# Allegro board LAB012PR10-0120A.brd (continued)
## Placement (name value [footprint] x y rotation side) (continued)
RV72  10K_0402_5%  [R_0402]  84.89 95.74 90 bottom
RV73  10K_0402_5%  [R_0402]  82.73 88.37 90 bottom
RV74  10K_0402_5%  [R_0402]  83.88 96.65 270 bottom
RV75  33_0402_5%  [R_0402]  82.86 96.65 270 bottom
RV76  33_0402_5%  [R_0402]  85.91 96.65 270 bottom
RV77  33_0402_5%  [R_0402]  79.23 90.35 0 bottom
RV78  33_0402_5%  [R_0402]  79.23 93.91 0 bottom
RV79  10K_0402_5%  [R_0402]  84.77 89.29 270 bottom
RV81  4.7K_0402_5%  [R_0402]  66.22 100.82 90 bottom
RV82  4.7K_0402_5%  [R_0402]  65.33 100.82 90 bottom
RV83  16.2K_0402_1%  [R_0402]  71.56 99.42 90 bottom
RV84  10K_0402_5%  [R_0402]  80.14 94.8 180 bottom
RV87  10K_0402_5%  [R_0402]  80.14 92.13 180 bottom
RV88  10K_0402_5%  [R_0402]  79.23 91.24 0 bottom
RV89  10K_0402_5%  [R_0402]  79.23 95.69 0 bottom
RV90  1K_0402_5%  [R_0402]  61.91 100.82 90 top
RV91  10K_0402_5%  [R_0402]  62.92 101.73 270 top
RV146  4.7K_0402_5%  [R_0402]  51.62 107.42 90 bottom
RV147  4.7K_0402_5%  [R_0402]  77.4 96.24 90 top
RV148  10K_0402_5%  [R_0402]  72.24 96.19 0 top
RV149  0_0402_5%  [R_0402]  72.24 97.08 0 top
RV150  10K_0402_5%  [R_0402]  60.56 91.88 0 top
RV151  10K_0402_5%  [R_0402]  62.85 101.73 270 bottom
RV152  10K_0402_5%  [R_0402]  61.96 100.82 90 bottom
RV153  0_0402_5%  [R_0402]  63.94 92.08 270 top
RV154  5.1K_0402_1%  [R_0402]  58.86 101.73 270 top
RV155  0_0402_5%  [R_0402]  79.23 88.57 0 bottom
RV156  0_0402_5%  [R_0402]  79.23 89.46 0 bottom
RV157  0_0402_5%  [R_0402]  79.23 93.02 0 bottom
RV158  0_0402_5%  [R_0402]  69.83 79.43 0 top
RV159  0_0402_5%  [R_0402]  69.83 80.7 0 top
RV160  0_0402_5%  [R_0402]  71.74 79.43 0 top
RV161  0_0402_5%  [R_0402]  71.74 80.7 0 top
RV162  4.7K_0402_5%  [R_0402]  79.89 77.02 180 bottom
RV163  4.7K_0402_5%  [R_0402]  78.97 76 0 bottom
RX2  100K_0402_5%  [R_0402]  8.82 76.59 270 top
RX3  100K_0402_5%  [R_0402]  8.74 74.73 0 top
RX7  0_0402_1%  [R0402_0OHM]  10.98 84.94 90 top
RX8  0_0402_5%  [R_0402]  10.09 84.94 90 top
RX9  10K_0402_5%  [R_0402]  4.17 80.07 0 top
RX10  10K_0402_5%  [R_0402]  24.46 74.88 270 top
RX12  10K_0402_5%  [R_0402]  197.21 74.22 0 top
RX13  100K_0402_5%  [R_0402]  199.89 84.08 270 top
RX14  100K_0402_5%  [R_0402]  197.21 75.11 0 top
RX15  150K_0402_5%  [R_0402]  197.21 73.33 0 top
RX16  2.2K_0402_5%  [R_0402]  196.35 76.38 0 top
RX17  2.2K_0402_5%  [R_0402]  196.35 77.53 0 top
RX21  0_0402_5%  [R_0402]  5.98 84.64 180 top
RX22  0_0402_5%  [R_0402]  5.98 85.65 180 top
RX23  0_0402_1%  [R0402_0OHM]  11.18 90.66 180 top
RX24  100K_0402_5%  [R_0402]  5.21 90.48 180 top
RX25  0_0402_1%  [R0402_0OHM]  9.45 93.6 270 top
RX26  100K_0402_5%  [R_0402]  4.17 81.08 0 top
RX27  0_0603_1%  [R0603_0OHM]  6.47 83.49 180 top
RX28  0_0603_1%  [R0603_0OHM]  9.65 99.12 0 top
RX29  0_0603_1%  [R0603_0OHM]  11.23 101.72 270 top
RX30  0_0603_5%  [R_0603]  9.71 101.72 270 top
RX34  20K_0402_5%  [R_0402]  198.13 72.45 180 top
RX35  100K_0402_5%  [R_0402]  5.21 89.29 180 top
RX36  0_0402_5%  [R_0402]  10.27 89.72 0 top
RX37  0_0402_5%  [R_0402]  7.55 104.65 270 top
RX38  0_0402_5%  [R_0402]  10.85 103.74 90 top
RX39  10K_0402_5%  [R_0402]  11.74 103.74 90 top
RX40  10K_0402_5%  [R_0402]  6.66 104.65 270 top
RX41  100K_0402_5%  [R_0402]  12.25 73.43 270 top
SW1  SMT1-05-A_4P  [SW_SMT1-05-A_4P]  172.28 113.17 90 top
T38  PAD  [TPC12]  143.19 89.74 0 top
T39  PAD  [TPC12]  118.9 93.68 0 top
T40  PAD  [TPC12]  117.58 94.09 0 top
T41  PAD  [TPC12]  120.07 94.92 0 top
T42  PAD  [TPC12]  116.03 93.78 0 top
T43  PAD  [TPC12]  120.17 93.32 0 top
T44  PAD  [TPC12]  117.66 88.73 0 top
T45  PAD  [TPC12]  119.18 89.23 0 top
T46  PAD  [TPC12]  120.55 89.26 0 top
T47  PAD  [TPC12]  118.4 87.43 0 top
T48  PAD  [TPC12]  118.5 90.66 0 top
T49  PAD  [TPC12]  120.86 86.49 0 top
T50  PAD  [TPC12]  119.06 92.23 0 top
T51  PAD  [TPC12]  120.02 90.89 0 top
T86  PAD  [TPC12]  57 98.32 0 top
T94  PAD~D  [TPC12]  173.59 106.63 0 bottom
T95  PAD~D  [TPC12]  175.42 107.17 180 top
T97  PAD  [TPC12]  163.38 87.89 0 top
T98  PAD  [TPC12]  155.89 89.21 0 top
T99  PAD  [TPC12]  158.35 87 0 top
T103  PAD~D  [TPC12]  154.97 83.06 0 top
T104  PAD~D  [TPC12]  153.98 87.18 0 top
T105  PAD  [TPC12]  154.56 84.95 0 top
T106  PAD  [TPC12]  156.9 83.62 0 top
T107  PAD  [TPC12]  152.18 87.18 0 top
T111  PAD  [TPC12]  117.86 98.4 0 top
T112  PAD  [TPC12]  116.44 98.4 0 top
T113  PAD  [TPC12]  120.07 96.45 0 top
T114  PAD  [TPC12]  116.95 96.75 0 top
T115  PAD  [TPC12]  117.46 95.36 0 top
T116  PAD  [TPC12]  118.55 96.91 0 top
T117  PAD  [TPC12]  155.07 87.96 0 top
T118  PAD~D  [TPC12]  150.42 81.72 0 top
T119  PAD~D  [TPC12]  150.22 83.16 0 top
T120  PAD~D  [TPC12]  147 100.26 0 top
T121  PAD~D  [TPC12]  148.65 100.26 0 top
T124  PAD~D  [TPC12]  158.73 92.99 180 bottom
T125  PAD~D  [TPC12]  158.27 90.17 180 bottom
T126  PAD~D  [TPC12]  153.12 86.21 0 top
T127  PAD~D  [TPC12]  157.79 85.15 0 top
T128  PAD~D  [TPC12]  156.9 81.72 0 top
T129  PAD~D  [TPC12]  143.06 95.56 0 top
T130  PAD~D  [TPC12]  141.48 95.48 0 top
T131  PAD~D  [TPC12]  141.59 93.91 0 top
T132  PAD~D  [TPC12]  128.48 82.55 0 top
T133  PAD~D  [TPC12]  146.28 92.05 0 top
T134  PAD~D  [TPC12]  128.96 80.7 0 top
T135  PAD~D  [TPC12]  148.75 101.76 0 top
T136  PAD~D  [TPC12]  159.11 85.15 0 top
T137  PAD~D  [TPC12]  150.27 84.44 0 top
T138  PAD~D  [TPC12]  143.08 99.78 0 top
T139  PAD~D  [TPC12]  153.19 81.69 0 top
T140  PAD~D  [TPC12]  142.73 98.18 0 top
T141  PAD~D  [TPC12]  150.07 80.4 0 top
T142  PAD~D  [TPC12]  147.38 81.34 0 top
T143  PAD~D  [TPC12]  143.47 96.93 0 top
T144  PAD~D  [TPC12]  147.25 79.33 0 top
T145  PAD~D  [TPC12]  148.65 79.05 0 top
T146  PAD~D  [TPC12]  113.11 74.99 0 top
T147  PAD~D  [TPC12]  112.96 78.87 0 top
T148  PAD~D  [TPC12]  115.12 101.53 0 top
T149  PAD~D  [TPC12]  116.52 101.53 0 top
T150  PAD~D  [TPC12]  129.67 103.51 0 top
T151  PAD~D  [TPC12]  125.63 105.36 0 top
T152  PAD~D  [TPC12]  124.59 103.38 0 top
T153  PAD~D  [TPC12]  114.81 93.4 0 top
T154  PAD~D  [TPC12]  118.75 95.15 0 top
T155  PAD~D  [TPC12]  141.71 92.33 0 top
T156  PAD~D  [TPC12]  143.21 91.11 0 top
T157  PAD~D  [TPC12]  111.74 76.97 0 top
T158  PAD~D  [TPC12]  119.31 103.05 0 top
T159  PAD~D  [TPC12]  153.26 102.73 0 top
T160  PAD~D  [TPC12]  144.79 93.02 0 top
T161  PAD~D  [TPC12]  157.41 99.59 0 top
T162  PAD~D  [TPC12]  143.36 92.41 0 top
T163  PAD~D  [TPC12]  157.41 100.96 0 top
T164  PAD~D  [TPC12]  146.75 98.77 0 top
T165  PAD~D  [TPC12]  145.98 97.46 0 top
T166  PAD~D  [TPC12]  110.6 74.3 0 top
T167  PAD~D  [TPC12]  155.87 102.65 0 top
T168  PAD~D  [TPC12]  154.83 103.44 0 top
T169  PAD~D  [TPC12]  117.15 103.94 0 top
T170  PAD~D  [TPC12]  116.16 102.93 0 top
T171  PAD~D  [TPC12]  158.55 81.46 0 top
T172  PAD~D  [TPC12]  157.28 80.19 0 top
T173  PAD~D  [TPC12]  110.83 75.9 0 top
T174  PAD~D  [TPC12]  153.35 90.99 0 top
T175  PAD~D  [TPC12]  154.36 95.31 0 top
T176  PAD~D  [TPC12]  152.14 98.28 0 top
T177  PAD~D  [TPC12]  151.67 94.72 0 top
T178  PAD~D  [TPC12]  147.63 102.42 0 top
T179  PAD~D  [TPC12]  158.04 96.45 0 top
T180  PAD~D  [TPC12]  158.04 98.34 0 top
T181  PAD~D  [TPC12]  158.07 98.99 180 bottom
T182  PAD~D  [TPC12]  153.27 84.48 0 top
T201  -  [TPC12]  62.16 89.72 0 top
T202  -  [TPC12]  59.77 89.87 0 top
T203  -  [TPC12]  71.56 91.5 0 top
T204  -  [TPC12]  67.98 89.97 0 top
T205  -  [TPC12]  70.8 92.64 0 top
T206  -  [TPC12]  72.83 90.86 0 top
T207  -  [TPC12]  69.2 90.43 0 top
T208  -  [TPC12]  70.19 94.24 0 top
T209  -  [TPC12]  71.35 90.15 0 top
T210  -  [TPC12]  69.27 93.02 0 top
T211  -  [TPC12]  68.23 91.7 0 top
T212  -  [TPC12]  66.99 91.11 0 top
T213  -  [TPC12]  67.49 92.79 0 top
T214  -  [TPC12]  67.11 94.09 0 top
T215  -  [TPC12]  69.14 95.69 0 top
T216  -  [TPC12]  65.72 90.73 0 top
T217  -  [TPC12]  66.07 92.54 0 top
T218  -  [TPC12]  70.16 85.65 0 top
T221  -  [TPC12]  67.62 95.31 0 top
T222  -  [TPC12]  69.53 97.08 0 top
T223  -  [TPC12]  62.24 98.23 180 bottom
T224  -  [TPC12]  62.83 96.88 180 bottom
T3861  PAD~D  [TPC12]  174.94 63.33 0 top
T3862  PAD~D  [TPC12]  176.21 63.56 0 top
T4927  PAD~D  [TPC12]  182.35 65.51 180 top
T4928  PAD~D  [TPC12]  183.7 65.46 180 top
T4929  PAD~D  [TPC12]  184.69 68.71 180 top
T4930  -  [TPC12]  76.64 89.97 180 bottom
TL2  350UH_LF-H1201P-2  [LANKO_LF-H1201P-2_16P]  180.59 102.04 90 bottom
U1  S IC SN74AVC2T45DCTR_SM8  [SN74LVC2T45DCTR_SM8]  81.63 94.31 0 bottom
U2301  -  [TPS22966DPUR_SON14_2X3]  169.42 13.13 0 top
U2302  64M EN25Q64-104HIP SOP 8P  [W25Q64FVSSIG_SO8]  184.08 18.6 180 bottom
U2303  -  [74AUP1G07GW_TSSOP5]  135.43 55.44 270 top
U2304  -  [TPS22966DPUR_SON14_2X3]  160.78 13.13 0 top
U2407  F75303M_MSOP10  [EMC1403-2-AIZL-TR_MSOP10]  154.76 8.32 0 top
U2408  TPS22967DSGR_SON8_2X2  [AOZ1336_DFN8_2X2]  154.73 22.62 180 top
UA1  -  [ALC3234-CG_MQFN48_6X6]  198.73 16.44 180 bottom
UC1  HASWELL-MCP-E-ULT_BGA1168  [HASWELL-MCP-E-ULT_BGA_1168P-T]  156.14 102.04 0 bottom
UC3  -  [MC74VHC1G08DFT2G_SC70-5]  171.25 94.04 270 top
UC4  -  [74CBTLV3126BQ_DHVQFN14_2P5X3]  88.52 86.97 90 top
UE1  KB9012QF-A4_LQFP128_14X14  [KB9012QF-A2_LQFP128_14X14]  130.99 17.71 270 top
UE2  -  [SN74LVC1G06DCKR_SC70-5]  110.66 25.87 180 top
UE3  APE8875M SOP 8P  [G993P1UF_SOP8]  6.79 69.57 180 top
UE4  TPS22967DSGR_SON8_2X2  [AOZ1336_DFN8_2X2]  8.82 65.08 270 top
UG1  -  [SLG3NB274VTR_TQFN16_2X3]  187.39 77.85 90 top
UI2  -  [AP2301MPG-13_MSOP8]  190.69 40.65 270 top
UI3  -  [AP2301MPG-13_MSOP8]  190.69 54.12 270 top
UI4  -  [AP2301MPG-13_MSOP8]  26.26 38.55 0 top
UI5  -  [SY6288D20AAC_SOT23-5]  194.21 46.92 90 top
UI6  -  [SY6288D20AAC_SOT23-5]  194 43.24 90 top
UI7  -  [SY6288D20AAC_SOT23-5]  24.69 41.5 180 top
UL1  RTL8106E-CG QFN 32P E-LAN CTRL  [RTL8106EUS-CG_QFN32_4X4]  177.62 104.96 270 bottom
UL2  -  [APL3512ABI-TRG_SOT23-5]  168.27 114.02 180 bottom
UL3  -  [SY6288C20AAC_SOT23-5]  189.47 95.63 180 bottom
UM1  -  [SY6288C20AAC_SOT23-5]  196.19 74.82 90 bottom
US2  -  [PS8520BTQFN20GTR2_TQFN20_4X4]  187.12 10.87 90 top
US3  LNG3DMTR_LGA16_3X3~D  [LNG3DMTR_LGA16_3X3]  20.36 16.86 180 bottom
UV1  2160856030-A0_FCBGA631  [216-0842024-A11-MAR_FCBGA_631P]  53.2 94.5 270 bottom
UV2  -  [MC74VHC1G08DFT2G_SC70-5]  78.18 77.84 180 top
UV3  -  [ADM1032ARMZ_MSOP8]  57.91 109.67 270 bottom
UV5  H5TC2G63FFR-11C FBGA 96P  [K4W1G1646E-HC12_FBGA_96P-A39]  42.95 72.12 90 bottom
UV6  H5TC2G63FFR-11C FBGA 96P  [K4W1G1646E-HC12_FBGA_96P-A39]  42.95 78.52 270 top
UV7  H5TC2G63FFR-11C FBGA 96P  [K4W1G1646E-HC12_FBGA_96P-A39]  42.95 98.33 270 top
UV8  H5TC2G63FFR-11C FBGA 96P  [K4W1G1646E-HC12_FBGA_96P-A39]  42.95 91.93 90 bottom
UX1  -  [APL3512ABI-TRG_SOT23-5]  12.06 83.57 180 top
UX3  -  [APL3512ABI-TRG_SOT23-5]  9.5 97.27 270 top
UX4  -  [SY6288C20AAC_SOT23-5]  21.27 74.08 0 top
YC1  32.768KHZ_12.5PF_Q13FC1350000  [Y_Q13FC1350000_2P]  176.08 74.08 270 top
YC2  24MHZ_12PF_X3G024000DC1H  [Y_X3G024000DC1H_4P]  136.79 109.31 180 bottom
YG1  25MHZ_10PF_7V25000014  [Y_FSX3M-25PM20FDO_4P]  187.47 74.52 180 top
YL2  25MHZ_10PF_7V25000014  [Y_FSX3M-25PM20FDO_4P]  176.8 108.6 180 bottom
YV1  27MHZ_10PF_7V27000050  [Y_7V27000011_4P]  82.57 73.8 270 bottom

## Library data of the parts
C35-C38 C50-C58 C61-C64 C67-C69 C71 C73 C75-C77 C79-C81 C83 C85 C87-C93 C2326 C2327 C2498 C2500 C2502 C2504 C2505 C4311-C4314 C4321 C4322 C5212-C5219 CA21 CA32 CA38-CA40 CA54 CA56 CA58 CA60 CA65 CA69 CC14-CC16 CC23 CC24 CC36 CC41 CC42 CE58-CE61 CG2-CG4 CG7-CG10 CI2 CI9 CI15 CI26 CI45-CI47 CL3 CL5-CL9 CL12 CL16 CL30 CL31 CL36 CL37 CL39 CL41 CM5 CM7 CM8 CS5 CS6 CS27 CS30-CS37 CS42 CS43 CV15 CV20 CV24 CV25 CV28 CV29 CV33 CV34 CV39-CV42 CV46-CV49 CV63-CV65 CV112 CV115-CV117 CV129-CV135 CV137-CV143 CV154 CV155 CV158-CV168 CV170-CV183 CVT90 CX1 CX2 CX4 CX9 CX11-CX21 CX23-CX30 CX50 CX52 PC2 PC7 PC8 PC13-PC17 PC108 PC116 PC117 PC202 PC210 PC214 PC520-PC523 PC526 PC527 PC529-PC531 PC541 PC545 PC546 PC548 PC601 PC603 PC604 PC733 PC840-PC852 PC859 PC860 PC869 PC871 PC872 PC1019 PC1022 PC1025 PC1027 PC1028 PC1030 PC1031 PC1033 PC1034 PC1036 PC1040 PC1042 PC1045 PC1047 PC1050 PC1051 PC1100 PC1101 PC1104 PC1106 PC1302 PC1304 PC1306 PC1307 = C_0402
C39-C47 C60 C66 C72 C74 C78 C82 C2305 C2306 C2308 C2309 C2311-C2318 C2322-C2325 C2328 C2329 CA55 CA57 CA59 CA61-CA64 CA67 CA68 CA71 CA74 CC37 CC38 CE56 CE57 CG6 CI40 CI43 CL4 CL13 CL14 CL17 CL38 CM4 CM6 CV19 CV38 CV43-CV45 CV67 CV68 CV118 CV136 CV151 CV169 CX5 CX22 PC103 PC104 PC106 PC312 PC313 PC525 PC528 PC853-PC858 PC1020 PC1021 PC1026 PC1029 PC1032 PC1035 PC1043 PC1044 PC1103 PC1105 = C_0603
C59 C65 C70 C84 C86 CL33 CM3 = C_1206
C2307 C2310 CG5 CI18 CI44 CS7 CS44 CX3 CX7 CX8 CX49 CX51 PC112 PC206 PC311 PC524 PC532 PC600 PC602 PC605 PC730 PC731 PC734-PC739 PC905-PC912 PC918-PC921 PC1023 PC1024 PC1041 PC1046 PC1048 PC1049 PC1052 PC1102 PC1300 PC1301 PC1303 PC1305 PC1308 = C_0805
CA1 CA2 = C_0603: room: AJACK
CA22 CA24 CA25 CA29-CA31 CA33 CA51 CV62 = C_0402: room: CODEC
CA23 CA53 CV61 = C_0603: room: CODEC
CC1-CC5 CC8 CC11 CC13 CC17-CC22 CC25 CC27-CC35 CC40 PC207 PC914 = C_0402: room: CPU
CC6 CC7 CC9 CC10 = C_0402: room: SPI
CC26 = C_0603: room: CPU
CD1-CD11 CD21-CD27 CD30-CD42 CD52-CD57 CD60 CD61 CD64 = C_0402: room: MEMORY
CD12-CD14 CD16-CD20 CD28 CD29 CD43-CD50 CD58 CD59 CD62 = C_0603: room: MEMORY
CD15 CD51 = C_D3: room: MEMORY
CD63 CD65 = C_D3
CE1 CE2 CE5-CE9 = C_0402: room: SIO
CE11 CE12 CE15 CE18-CE20 CE23 CE24 CE26-CE31 CE34 = C_0402: room: KBC
CE16 = C_0805: room: KBC
CE22 CE25 = C_0603: room: KBC
CE32 = C_0402: room: FAN
CE35 CE36 = C_0402: room: THERMAL
CI1 CI8 = C_MP6VLPS220MC4R2: room: USB
CI3 CI4 CI7 CI10 CI11 CI13 CI14 CI17 = C_0402: room: USB
CI6 CI12 = C_0805: room: USB
CL15 = C_0402: room: LAN
CL19 CV17 CV18 CV21 CV23 CV26 = C_0402: room: HDMI
CMOS1 = SHORTPADS: User Part Number: PART#; room: CPU
CV1-CV11 = C_0402: room: EDP
CV22 CV27 = C_0603: room: HDMI
CV50-CV53 CV56-CV59 CV124-CV128 CV144 = C_0402: room: CRT
CV54 CV55 = C_0603: room: CRT
CV60 CV66 CV71-CV80 CV145-CV150 CV152 CV153 CV156 CV157 = C_0402: room: DP12412
CV69 CV70 = C_0603: room: DP12412
CV81 = C_0603: room: TOUCH
CV82 CV85-CV87 CV89 CV90 CV92-CV102 CV104-CV111 CV113 CV114 = C_0402: room: DP2320
CV83 CV84 CV88 CV91 CV103 = C_0603: room: DP2320
CV119-CV123 = C_0402: room: DP125
DA8 = BAT54C-7-F_SOT23-3
DA10 DA12-DA14 = AZ5125-02SPR7G_SOT23-3
DC1 = BAT54CW_SOT323-3
DE1 = L03ESDL5V0CG3-2_SOT-523-3: room: FAN
DE2 = L03ESDL5V0CC3-2_SOT23-3
DE3 DE4 DH1 DX1 = RB751V-40_SOD323-2
DI1 DI4 = IP4292CZ10-TBR_XSON10_2P5X1: room: USB
DI2 DI5 = L30ESDL5V0C3-2_SOT23-3: room: USB
DS1 = SDM10U45-7_SOD523-2
DX2 = PESD5V0U2BT_SOT23-3
FD1-FD4 = FIDUCIAL_C40M80: room: LED
FE1 = F_1812L075-24DR
FX1 = F_1206L150PR
H1 H20 = H_2P8N: room: LED
H2-H8 H11 H12 = H_2P8: room: LED
H9 = H_2P8
H10 = H_3P0
H13-H16 = H_3P6: room: LED
H17-H19 = H_3P3: room: LED
H21 = H_2P8N
H22 = H_2P8X3P3N
H23 = H_2P8X4P8N
HE1 LV2 LV4 LV7 LV8 LV26 PH1 PH1002 PH1003 PR3 PR4 PR20 PR23-PR37 PR110 PR115 PR204 PR304 PR309 PR310 PR525 PR533 PR537 PR543 PR545 PR549 PR551 PR558 PR602-PR604 PR719 PR727 PR1020 PR1025 PR1029-PR1033 PR1035 PR1037 PR1038 PR1040-PR1048 PR1051-PR1053 PR1056 PR1058 PR1059 PR1102 PR1105 PR1107 PR1108 PR1110 PR1300-PR1302 PR1304 R1 R2 R10 R16 R159 R286 R2313 R2318 R2329-R2338 R2341 R2346-R2352 R2354 R2356-R2359 R2448 R2450-R2453 RA10-RA13 RA19 RA53 RA55 RA56 RA79-RA84 RA130 RA165 RA166 RA1109 RA1112 RA1113 RC3 RC5 RC6 RC12 RC13 RC24 RC27 RC28 RC32 RC36 RC39 RC48 RC49 RC51 RC52 RC56 RC58 RC60 RC64 RC71 RC73 RC75 RC76 RC79 RC84 RC90 RC97 RC100 RC101 RC104 RC105 RC107-RC111 RC114 RC115 RC134-RC138 RC142 RC143 RC362-RC364 RC367 RC368 RE1-RE3 RE7 RE18 RE47 RE49 RE50 RE72 RE73 RE326 RE329 RE332-RE335 RE338-RE340 RG1-RG6 RG8 RL27 RL31 RL33-RL35 RL37-RL40 RM8-RM10 RS8 RS18-RS38 RV21-RV23 RV25 RV26 RV28 RV29 RV39-RV49 RV59 RV146-RV163 RX2 RX3 RX8-RX10 RX12-RX17 RX21 RX22 RX24 RX26 RX34-RX41 = R_0402
J9 J518-J520 JP3 JP12 JP14 PJP301 = JUMP_43X39
J510-J516 JP13 PJP600 PJP601 PJP1300 PJP1301 = JUMP_43X79
JDIMM1 = BELLW_80001-1021_204P: room: CPU
JDIMM2 = BELLW_80011-1021_204P: room: CPU
JEDP = STARC_107K40-000001-G2_40P
JFAN = ACES_88231-03041_3P
JHDD = E-T_4260K-F10N-00L_10P
JHDMI = CONCR_099ATAC19NBLCNF_19P
JHP = SINGA_2SJ3080-001111F_6P
JIO = ACES_51524-0160N-001_16P
JKB = HB_A823020-SBHR21_30P
JKBBL = ACES_50524-00401-P01_4P-T
JLAN = SDAN_601028-008041_8P-T
JLED JTP = ACES_51524-0080N-001_8P
JNGFF = LOTES_APCI0019-P009A_67P
JRTC = ACES_50271-0020N-001_2P
JSPK = ACES_50278-00401-001_4P
JTP1 = ACES_51524-0100N-001_10P
JUSB1 JUSB2 = TAITW_PUBAU6-09FLBS1NN4H0_9P: room: USB
JXDP1 = SAMTE_BSH-030-01-L-D-A_60P: room: CPU
L1-L5 LL1 = MURAT_LQM2MPN2R2NG0L_2P
LA1 = MURAT_BLM15BB221SN1D_2P
LA3 = R_0603: room: AJACK
LA4 PR210 PR538 PR605 PR1024 PR1034 PR1039 PR1055 PR1057 PR1101 R245 R2314 R2315 RE328 RE330 RE331 RV24 RV60 RX30 = R_0603
LA5 LA6 = R_0603: room: CODEC
LA7 = MURAT_BLM15BD601SN1D_2P: room: CODEC
LA8 LA9 = KC_FBMA-L10-160808-800LMT_2P: room: CODEC
LA10 = MURAT_BLM15BD601SN1D_2P
LE1 LE2 = KC_FBMA-L11-160808-800LMT_2P
LI1 LI3 LI4 LI6 = MURAT_DLW21SN670HQ2L_4P: room: USB
LI2 LI5 = KC_WCM-2012HS-900T_4P: room: USB
LI7 LI8 LX2-LX6 = KC_WCM-2012HS-900T_4P
LV3 RV8 RV9 RV11-RV13 RV15-RV17 RV20 = R_0402: room: HDMI
LV6 = MURAT_BLM15BB221SN1D_2P: room: HDMI
LV25 RV73-RV79 RV81-RV84 RV87-RV89 = R_0402: room: DP2320
LX1 = KC_FBMA-L11-201209-221LMA30_2P
PBATT = ALLTO_C144LS-109A9-L_9P-T
PC1 PC3-PC5 = C_0402: room: P_DCIN
PC100 PC105 PC109-PC111 PC200 PC204 PC209 PC301 PC302 PC401 = C_0603: room: ETY-ROOM
PC101 = C_MP6VLPS220MC4R2: room: ETY-ROOM
PC102 PC114 PC201 PC203 PC300 PC303 PC304 PC307 PC400 PC402 PC403 PC500 PC510 PC519 = C_0402: room: ETY-ROOM
PC107 = C_MP6VLPS220MC4R2
PC113 = C_0402: room: 3V5V
PC115 = C_0805: room: 3V5V
PC205 PC211 PC212 PC305 PC306 PC308-PC310 PC404 = C_0805: room: ETY-ROOM
PC208 = C_0402: room: ADP3209
PC213 = C_MP6VU330MC6: room: CPU_CORE
PC515 PC516 = C_EEEFZ1E101P: room: CPU_CORE
PC517 PC518 = C_0805: room: CPU_CORE
PC701 PC702 PC705-PC708 PC711 PC715 PC717 PC720 PC723-PC728 = C_0402: room: CHARGER
PC703 PC704 PC712-PC714 PC716 PC718 = C_0805: room: CHARGER
PC709 PC710 PC719 PC722 = C_0603: room: CHARGER
PC721 = C_0603: room: ADP3209
PC729 = C_0805: room: P_SELECTOR
PC732 = C_EEEFZ1E101P
PC836-PC839 = C_D2
PC901-PC904 PC913 PC915-PC917 PC922 PC923 = C_0805: room: CPU
PC924 = C_D2: room: CPU
PC1108 = C_MP6VU330MC6
PD1 PD2 = TVNST52302AB0_SOT523-3: room: ETY-ROOM
PD101 = TVNST52302AB0_SOT523-3
PD700 = BAS40CW_SOT323-3
PH500 PH501 PR102 PR104-PR108 PR114 PR205 PR207 PR208 PR301 PR305 PR307 PR400-PR403 PR500 PR512 PR528 PR539 PR701 PR706 PR707 = R_0402: room: ETY-ROOM
PJP100-PJP102 PJP300 = JUMP_43X118: room: ETY-ROOM
PJP103 PJP1100 PJP1101 = JUMP_43X118
PJP200 = JUMP_43X118: room: DDR_VTT_0.75V
PJP201 = JUMP_43X118: room: VGA_CORE
PJP203 = JUMP_43X39: room: ETY-ROOM
PJP400 PJP401 = JUMP_43X79: room: VGA_CORE
PJPDC = ACES_50299-00501-003_5P
PL1 PL3 PL4 = TAIYO_FBMJ4516HS720NT_2P: room: P_DCIN
PL2 = MURAT_BLM15AG102SN1D_2P: room: P_DCIN
PL5 PL201 PL302 PL1000 PL1100 = TAIYO_FBMJ4516HS720NT_2P
PL6 PL7 PL503 PL1004 = CYNTE_PCMB053T-1R0MS_2P-S
PL100 PL101 PL200 = PANAS_ETQP3W2R2WFN_2P: room: ETY-ROOM
PL102 = L_5X5X3_M_2P: room: VDDCI
PL301 = L_5X5X3_M_2P: room: ETY-ROOM
PL501 = TAIYO_FBMJ4516HS720NT_2P: room: CPU_CORE
PL502 = TOKO_FDUE1040J-H-R36M-P3_4P
PL600 = TAIYO_NRS4018T1R0NDGJ_2P
PL701 = CYNTE_PCMB104T-1R0MH_2P: room: ETY-ROOM
PL702 = L_5X5X3_M_2P
PL1002 PL1003 = PANAS_ETQP4LR15AFM_4P
PL1101 PL1300 = PANAS_ETQP3W2R2WFN_2P
PQ1-PQ3 = 2N7002DW-T-R7_SOT363-6: room: P_DCIN
PQ4 = 2N7002DW-T-R7_SOT363-6: room: ETY-ROOM
PQ5 = RHU002N06_SOT323-3
PQ6 = FDV301N_NL_SOT23-3: room: ETY-ROOM
PQ101-PQ103 = SIS412DN-T1-GE3_POWERPAK8-5: room: ETY-ROOM
PQ104 PQ200 PQ201 PQ1100 PQ1101 = SIS412DN-T1-GE3_POWERPAK8-5
PQ501 = CSD86350Q5D_SON8
PQ700 = AO4407AL_SO8: room: CHARGER
PQ701 = AO4409L_SO8: room: ETY-ROOM
PQ702 = AO4407AL_SO8: room: ETY-ROOM
PQ703 = SIR472DP-T1-GE3_POWERPAK8-5: room: ETY-ROOM
PQ705 = SIRA06DP-T1-GE_POWERPAKSO-8-5
PQ706 = 2N7002DW-T-R7_SOT363-6
PQ1003 PQ1005 = MDU1516URH_POWERDFN56-8-5
PQ1004 PQ1006-PQ1008 = SIR472DP-T1-GE3_POWERPAK8-5
PR1 PR2 PR6-PR11 PR15 PR16 PR18 = R_0402: room: P_DCIN
PR5 PR1036 PR1054 PR1104 PR1303 RM7 = R_1206
PR100 PR101 PR201 PR202 = R0402_0OHM: room: ETY-ROOM
PR103 PR111 PR206 PR536 = R_0603: room: ETY-ROOM
PR109 PR519 = R_0402: room: CPU_CORE
PR112 PR113 PR203 PR302 PR534 PR722 = R_1206: room: ETY-ROOM
PR200 = R_0603: room: CPU_CORE
PR209 PR300 PR552 PR601 PR1022 PR1027 PR1049 PR1050 PR1060-PR1063 PR1103 R248 R250 R251 R416 RC26 RC37 RC41-RC46 RC57 RC59 RC82 RC365 RC366 RD1 RD8 RE44 RE336 RE337 RM5 RM6 RX7 RX23 RX25 = R0402_0OHM
PR303 = R0603_0OHM: room: ETY-ROOM
PR306 PR308 = R_0402: room: 1P5V
PR503 PR504 PR507 PR521 PR535 = R_0402: room: GPU_CORE
PR505 PR506 PR508 PR510 PR511 = R0402_0OHM: room: GPU_CORE
PR702 = R_1206_4P-D: room: ETY-ROOM
PR704 PR708 PR711 PR713 PR717 PR718 PR723-PR726 PR728 = R_0402: room: CHARGER
PR705 PR720 = R_1206: room: CHARGER
PR709 PR710 = R_0603: room: CHARGER
PR712 = R_0402: room: 3V5V
PR714 PR715 = R0402_0OHM: room: CHARGER
PR716 = R_1206_4P-D: room: CHARGER
PU100 = TPS51285BRUKR_QFN20_3X3: room: ETY-ROOM
PU200 = RT8207MZQW_WQFN20_3X3: room: ETY-ROOM
PU300 = SY8206DQNC_QFN10_3X3: room: ETY-ROOM
PU400 = APL5930KAI-TRG_SO8: room: ETY-ROOM
PU501 = ISL95813HRZ-T_QFN20_3X4: room: ETY-ROOM
PU600 = SY8003DFC_DFN8_2X2
PU701 = ISL9520HRTZ-T_TQFN28_4X4: room: ETY-ROOM
PU1000 = ISL62771HRTZ-T_TQFN40_5X5
PU1100 = TPS51212DSCR_SON10_3X3
PU1300 = SY8036DBC_DFN10_3X3
Q8 Q2307 Q2308 QC3 QX3 = 2N7002K_SOT23-3
Q2407 Q2408 = MMST3904-7-F_SOT323-3
Q2409 QM1 QS1 = SSM3K7002FU_SC70-3
QA5 QA6 QC2 QE6 QH1 QX4 QX6 = DMN66D0LDW-7_SOT363-6
QC1 = DMN66D0LDW-7_SOT363-6: room: CPU
QD2 = BSS138-G_SOT23-3
QE4 = 2N7002BKW_SOT323-3: room: THERMAL
QE5 = SI3456BDV-T1-E3_TSOP6: room: THERMAL
QV1 = 2N7002KDWH_SOT363-6: room: EDP
QV2 = AO3413_SOT23-3: room: EDP
QV3 QV4 = 2N7002K_SOT23-3: room: HDMI
QV8 = DMN66D0LDW-7_SOT363-6: room: TOUCH
QX1 = 2N7002KW_SOT323-3
QX2 = SI3457CDV-T1-GE3_TSOP6
QX5 = MMBT3904_NL_SOT23-3
R252-R256 = R_0402: room: DOCK
R257 = R0402_0OHM: room: DOCK
R264 = R0603_0OHM: room: DOCK
R267 = R0805_0OHM: room: DOCK
RA1 RA2 = R_0402: room: AJACK
RA3-RA9 = R_0402: room: CODEC
RA29-RA32 = R0603_0OHM: room: CODEC
RA1110 RA1111 RE327 RL6 RV27 RV30 RX27-RX29 = R0603_0OHM
RC1 RC2 RC4 RC7-RC11 RC14-RC23 RC25 RC33 RC34 RC63 RC65-RC70 RC72 RC74 RC77 RC78 RC87-RC89 RC91 RC98 RC99 RC102 RC103 RC106 RC112 RC113 RC116 RC118-RC125 RC127-RC133 RC139 RC140 RC163 = R_0402: room: CPU
RC29 RC31 = R_0402: room: FLASH ROM
RC35 RC50 RC62 = R_0402: room: SPI
RC38 = R0402_0OHM: room: SPI
RC81 RC141 = R0402_0OHM: room: CPU
RC126 = R0603_0OHM: room: CPU
RD3 RD6 RD7 RD12 RD13 = R_0402: room: MEMORY
RD4 RD5 RD10 = R0402_0OHM: room: MEMORY
RE5 RE8-RE10 RE12 = R_0402: room: SIO
RE36 RE43 RE58 RE60 RE68 RE71 = R_0402: room: KBC
RE37 = R0402_0OHM: room: KBC
RE59 = R_0805: room: KBC
RL1 = MURAT_BLM18AG601SN1D_L0603_2P
RL19 RL20 = R_0603: room: LOM
RP34 RP36 RP37 RP39-RP42 RP44-RP46 RP48-RP55 RP58 RP59 = RP_0804_8P4R
RV1-RV6 = R_0402: room: EDP
RV31 = R0805_0OHM
RV32-RV38 = R_0402: room: CRT
RV50-RV58 RV71 RV72 = R_0402: room: DP12412
RV90 RV91 = R_0402: room: DP125
SW1 = SW_SMT1-05-A_4P: room: CPU
T38-T51 T86 T94 T95 T99 T103-T107 T111-T121 T124-T182 T201-T218 T221-T224 T3861 T3862 T4927-T4930 = TPC12
T97 T98 = TPC12: room: SIO
TL2 = LANKO_LF-H1201P-2_16P
U1 = SN74LVC2T45DCTR_SM8
U2301 U2304 = TPS22966DPUR_SON14_2X3
U2302 = W25Q64FVSSIG_SO8
U2303 = 74AUP1G07GW_TSSOP5
U2407 = EMC1403-2-AIZL-TR_MSOP10
U2408 UE4 = AOZ1336_DFN8_2X2
UA1 = ALC3234-CG_MQFN48_6X6: room: CODEC
UC1 = HASWELL-MCP-E-ULT_BGA_1168P-T: room: CPU
UC3 = MC74VHC1G08DFT2G_SC70-5: room: SPI
UC4 = 74CBTLV3126BQ_DHVQFN14_2P5X3: room: CPU
UE1 = KB9012QF-A2_LQFP128_14X14: room: SIO
UE2 = SN74LVC1G06DCKR_SC70-5: room: KBC
UE3 = G993P1UF_SOP8
UG1 = SLG3NB274VTR_TQFN16_2X3
UI2 UI3 = AP2301MPG-13_MSOP8: room: USB
UI4 = AP2301MPG-13_MSOP8
UI5-UI7 = SY6288D20AAC_SOT23-5
UL1 = RTL8106EUS-CG_QFN32_4X4: room: LAN
UL2 = APL3512ABI-TRG_SOT23-5: room: LAN
UL3 UM1 UX4 = SY6288C20AAC_SOT23-5
US2 = PS8520BTQFN20GTR2_TQFN20_4X4
US3 = LNG3DMTR_LGA16_3X3
UV1 = 216-0842024-A11-MAR_FCBGA_631P: room: EDP
UV2 = MC74VHC1G08DFT2G_SC70-5: room: HDMI
UV3 = ADM1032ARMZ_MSOP8
UV5 UV6 = K4W1G1646E-HC12_FBGA_96P-A39
UV7 UV8 = K4W1G1646E-HC12_FBGA_96P-A39: room: DP125
UX1 UX3 = APL3512ABI-TRG_SOT23-5
YC1 = Y_Q13FC1350000_2P: room: CPU
YC2 = Y_X3G024000DC1H_4P: room: CPU
YG1 YL2 = Y_FSX3M-25PM20FDO_4P
YV1 = Y_7V27000011_4P

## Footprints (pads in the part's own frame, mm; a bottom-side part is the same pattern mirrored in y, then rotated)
2N7002BKW_SOT323-3
  oval 0.61x0.559 smd: 1(0,0) 2(-0.65,-1.85) 3(0.65,-1.85)
2N7002DW-T-R7_SOT363-6
  oval 0.381x1.397 smd: 1(0,0) 2(0.65,0) 3(1.3,0) 4(1.3,1.725) 5(0.65,1.725) 6(0,1.725)
2N7002K_SOT23-3
  oval 1.016x1.524 smd: 1(0,0) 2(0.965,2.083) 3(-0.965,2.083)
2N7002KDWH_SOT363-6
  oval 0.356x0.889 smd: 1(0,0) 2(0.65,0) 3(1.3,0) 4(1.3,1.6) 5(0.65,1.6) 6(0,1.6)
2N7002KW_SOT323-3
  oval 0.813x0.914 smd: 1(0,0) 2(0.65,1.6) 3(-0.65,1.6)
74AUP1G07GW_TSSOP5
  oval 0.381x1.346 smd: 1(0,0) 2(0.65,0) 3(1.3,0) 4(1.3,1.79) 5(0,1.79)
74CBTLV3126BQ_DHVQFN14_2P5X3
  oval 1.041x0.254 smd: 1(0,0) 7(2.95,0) 8(2.95,0.5) 14(0,0.5)
  oval 0.254x1.041 smd: 2(0.475,-0.975) 3(0.975,-0.975) 4(1.475,-0.975) 5(1.975,-0.975) 6(2.475,-0.975) 9(2.475,1.475) 10(1.975,1.475) 11(1.475,1.475) 12(0.975,1.475) 13(0.475,1.475)
  rect 1.499x0.991 smd: 15(1.475,0.25)
216-0842024-A11-MAR_FCBGA_631P
  round 0.406 smd: A3(0.8,0) A30(20.8,0) A32(21.6,0) AB7(3.2,-15) AB8(4,-15) AB9(4.8,-15) AB10(5.6,-15) AB23(16,-15) AB24(16.8,-15) AB25(17.6,-15) AB26(18.4,-15) AC11(6.6,-16) AC13(7.8,-16) AC14(9,-16) AC16(10.2,-16) AC17(11.4,-16) AC19(12.6,-16) AC20(13.8,-16) AC22(15,-16) AD11(6.6,-16.8) AD13(7.8,-16.8) AD14(9,-16.8) AD16(10.2,-16.8) AD17(11.4,-16.8) AD19(12.6,-16.8) AD20(13.8,-16.8) AD22(15,-16.8) AE11(6.6,-17.6) AE13(7.8,-17.6) AE14(9,-17.6) AE16(10.2,-17.6) AE17(11.4,-17.6) AE19(12.6,-17.6) AE20(13.8,-17.6) AE22(15,-17.6) AF11(6.6,-18.4) AF13(7.8,-18.4) AF14(9,-18.4) AF16(10.2,-18.4) AF17(11.4,-18.4) AF19(12.6,-18.4) AF20(13.8,-18.4) AF22(15,-18.4) AK1(0,-20.8) AK3(0.8,-20.8) AK30(20.8,-20.8) AK32(21.6,-20.8) AM1(0,-21.6) AM3(0.8,-21.6) AM30(20.8,-21.6) AM32(21.6,-21.6) C1(0,-0.8) C3(0.8,-0.8) C30(20.8,-0.8) C32(21.6,-0.8) G11(6.6,-3.2) G13(7.8,-3.2) G14(9,-3.2) G16(10.2,-3.2) G17(11.4,-3.2) G19(12.6,-3.2) G20(13.8,-3.2) G22(15,-3.2) H11(6.6,-4) H13(7.8,-4) H14(9,-4) H16(10.2,-4) H17(11.4,-4) H19(12.6,-4) H20(13.8,-4) H22(15,-4) J11(6.6,-4.8) J13(7.8,-4.8) J14(9,-4.8) J16(10.2,-4.8) J17(11.4,-4.8) J19(12.6,-4.8) J20(13.8,-4.8) J22(15,-4.8) K11(6.6,-5.6) K13(7.8,-5.6) K14(9,-5.6) K16(10.2,-5.6) K17(11.4,-5.6) K19(12.6,-5.6) K20(13.8,-5.6) K22(15,-5.6) L7(3.2,-6.6) L8(4,-6.6) L9(4.8,-6.6) L10(5.6,-6.6) L23(16,-6.6) L24(16.8,-6.6) L25(17.6,-6.6) L26(18.4,-6.6) N7(3.2,-7.8) N8(4,-7.8) N9(4.8,-7.8) N10(5.6,-7.8) N23(16,-7.8) N24(16.8,-7.8) N25(17.6,-7.8) N26(18.4,-7.8) P7(3.2,-9) P8(4,-9) P9(4.8,-9) P10(5.6,-9) P23(16,-9) P24(16.8,-9) P25(17.6,-9) P26(18.4,-9) T7(3.2,-10.2) T8(4,-10.2) T9(4.8,-10.2) T10(5.6,-10.2) T23(16,-10.2) T24(16.8,-10.2) T25(17.6,-10.2) T26(18.4,-10.2) U7(3.2,-11.4) U8(4,-11.4) U9(4.8,-11.4) U10(5.6,-11.4) U23(16,-11.4) U24(16.8,-11.4) U25(17.6,-11.4) U26(18.4,-11.4) W7(3.2,-12.6) W8(4,-12.6) W9(4.8,-12.6) W10(5.6,-12.6) W23(16,-12.6) W24(16.8,-12.6) W25(17.6,-12.6) W26(18.4,-12.6) Y7(3.2,-13.8) Y8(4,-13.8) Y9(4.8,-13.8) Y10(5.6,-13.8) Y23(16,-13.8) Y24(16.8,-13.8) Y25(17.6,-13.8) Y26(18.4,-13.8)
  round 0.305 smd: A5(1.6,0) A7(3.2,0) A9(4.8,0) A11(6.4,0) A13(8,0) A15(9.6,0) A17(11.2,0) A19(12.8,0) A21(14.4,0) A23(16,0) A25(17.6,0) A27(19.2,0) A28(20,0) AA1(0,-14.4) AA3(0.8,-14.4) AA5(1.6,-14.4) AA6(2.4,-14.4) AA27(19.2,-14.4) AA29(20.4,-14.4) AA31(21.2,-14.4) AB2(0.4,-15.2) AB4(1.2,-15.2) AB6(2.4,-15.2) AB27(19.2,-15.2) AB28(20,-15.2) AB30(20.8,-15.2) AB32(21.6,-15.2) AC1(0,-16) AC3(0.8,-16) AC5(1.6,-16) AC6(2.4,-16) AC7(3.2,-16) AC8(4,-16) AC9(4.8,-16) AC10(5.6,-16) AC23(16,-16) AC24(16.8,-16) AC25(17.6,-16) AC26(18.4,-16) AC27(19.2,-16) AC29(20.4,-16) AC31(21.2,-16) AD2(0.4,-16.8) AD4(1.2,-16.8) AD6(2.4,-16.8) AD7(3.2,-16.8) AD8(4,-16.8) AD9(4.8,-16.8) AD10(5.6,-16.8) AD23(16,-16.8) AD24(16.8,-16.8) AD25(17.6,-16.8) AD26(18.4,-16.8) AD27(19.2,-16.8) AD28(20,-16.8) AD30(20.8,-16.8) AD32(21.6,-16.8) AE1(0,-17.6) AE3(0.8,-17.6) AE5(1.6,-17.6) AE6(2.4,-17.6) AE7(3.2,-17.6) AE8(4,-17.6) AE9(4.8,-17.6) AE10(5.6,-17.6) AE23(16,-17.6) AE24(16.8,-17.6) AE25(17.6,-17.6) AE26(18.4,-17.6) AE27(19.2,-17.6) AE29(20.4,-17.6) AE31(21.2,-17.6) AF2(0.4,-18.4) AF4(1.2,-18.4) AF6(2.4,-18.4) AF7(3.2,-18.4) AF8(4,-18.4) AF9(4.8,-18.4) AF10(5.6,-18.4) AF23(16,-18.4) AF24(16.8,-18.4) AF25(17.6,-18.4) AF26(18.4,-18.4) AF27(19.2,-18.4) AF28(20,-18.4) AF30(20.8,-18.4) AF32(21.6,-18.4) AG1(0,-19.2) AG3(0.8,-19.2) AG5(1.6,-19.2) AG6(2.4,-19.2) AG7(3.2,-19.2) AG8(4,-19.2) AG9(4.8,-19.2) AG10(5.6,-19.2) AG11(6.4,-19.2) AG12(7.2,-19.2) AG13(8,-19.2) AG14(8.8,-19.2) AG15(9.6,-19.2) AG16(10.4,-19.2) AG17(11.2,-19.2) AG18(12,-19.2) AG19(12.8,-19.2) AG20(13.6,-19.2) AG21(14.4,-19.2) AG22(15.2,-19.2) AG23(16,-19.2) AG24(16.8,-19.2) AG25(17.6,-19.2) AG26(18.4,-19.2) AG27(19.2,-19.2) AG29(20.4,-19.2) AG31(21.2,-19.2) AH1(0,-20) AH3(0.8,-20) AH5(1.6,-20) AH6(2.4,-20) AH8(4,-20) AH10(5.6,-20) AH12(7.2,-20) AH14(8.8,-20) AH16(10.4,-20) AH18(12,-20) AH20(13.6,-20) AH22(15.2,-20) AH24(16.8,-20) AH26(18.4,-20) AH28(20,-20) AH30(20.8,-20) AH32(21.6,-20) AJ7(3.2,-20.4) AJ9(4.8,-20.4) AJ11(6.4,-20.4) AJ13(8,-20.4) AJ15(9.6,-20.4) AJ17(11.2,-20.4) AJ19(12.8,-20.4) AJ21(14.4,-20.4) AJ23(16,-20.4) AJ25(17.6,-20.4) AJ27(19.2,-20.4) AK5(1.6,-20.8) AK6(2.4,-20.8) AK8(4,-20.8) AK10(5.6,-20.8) AK12(7.2,-20.8) AK14(8.8,-20.8) AK16(10.4,-20.8) AK18(12,-20.8) AK20(13.6,-20.8) AK22(15.2,-20.8) AK24(16.8,-20.8) AK26(18.4,-20.8) AK28(20,-20.8) AL7(3.2,-21.2) AL9(4.8,-21.2) AL11(6.4,-21.2) AL13(8,-21.2) AL15(9.6,-21.2) AL17(11.2,-21.2) AL19(12.8,-21.2) AL21(14.4,-21.2) AL23(16,-21.2) AL25(17.6,-21.2) AL27(19.2,-21.2) AM5(1.6,-21.6) AM6(2.4,-21.6) AM8(4,-21.6) AM10(5.6,-21.6) AM12(7.2,-21.6) AM14(8.8,-21.6) AM16(10.4,-21.6) AM18(12,-21.6) AM20(13.6,-21.6) AM22(15.2,-21.6) AM24(16.8,-21.6) AM26(18.4,-21.6) AM28(20,-21.6) B6(2.4,-0.4) B8(4,-0.4) B10(5.6,-0.4) B12(7.2,-0.4) B14(8.8,-0.4) B16(10.4,-0.4) B18(12,-0.4) B20(13.6,-0.4) B22(15.2,-0.4) B24(16.8,-0.4) B26(18.4,-0.4) C5(1.6,-0.8) C7(3.2,-0.8) C9(4.8,-0.8) C11(6.4,-0.8) C13(8,-0.8) C15(9.6,-0.8) C17(11.2,-0.8) C19(12.8,-0.8) C21(14.4,-0.8) C23(16,-0.8) C25(17.6,-0.8) C27(19.2,-0.8) C28(20,-0.8) D6(2.4,-1.2) D8(4,-1.2) D10(5.6,-1.2) D12(7.2,-1.2) D14(8.8,-1.2) D16(10.4,-1.2) D18(12,-1.2) D20(13.6,-1.2) D22(15.2,-1.2) D24(16.8,-1.2) D26(18.4,-1.2) E1(0,-1.6) E3(0.8,-1.6) E5(1.6,-1.6) E7(3.2,-1.6) E9(4.8,-1.6) E11(6.4,-1.6) E13(8,-1.6) E15(9.6,-1.6) E17(11.2,-1.6) E19(12.8,-1.6) E21(14.4,-1.6) E23(16,-1.6) E25(17.6,-1.6) E27(19.2,-1.6) E28(20,-1.6) E30(20.8,-1.6) E32(21.6,-1.6) F2(0.4,-2.4) F4(1.2,-2.4) F6(2.4,-2.4) F7(3.2,-2.4) F8(4,-2.4) F9(4.8,-2.4) F10(5.6,-2.4) F11(6.4,-2.4) F12(7.2,-2.4) F13(8,-2.4) F14(8.8,-2.4) F15(9.6,-2.4) F16(10.4,-2.4) F17(11.2,-2.4) F18(12,-2.4) F19(12.8,-2.4) F20(13.6,-2.4) F21(14.4,-2.4) F22(15.2,-2.4) F23(16,-2.4) F24(16.8,-2.4) F25(17.6,-2.4) F26(18.4,-2.4) F27(19.2,-2.4) F28(20,-2.4) F30(20.8,-2.4) F32(21.6,-2.4) G1(0,-3.2) G3(0.8,-3.2) G5(1.6,-3.2) G6(2.4,-3.2) G7(3.2,-3.2) G8(4,-3.2) G9(4.8,-3.2) G10(5.6,-3.2) G23(16,-3.2) G24(16.8,-3.2) G25(17.6,-3.2) G26(18.4,-3.2) G27(19.2,-3.2) G29(20.4,-3.2) G31(21.2,-3.2) H2(0.4,-4) H4(1.2,-4) H6(2.4,-4) H7(3.2,-4) H8(4,-4) H9(4.8,-4) H10(5.6,-4) H23(16,-4) H24(16.8,-4) H25(17.6,-4) H26(18.4,-4) H27(19.2,-4) H28(20,-4) H30(20.8,-4) H32(21.6,-4) J1(0,-4.8) J3(0.8,-4.8) J5(1.6,-4.8) J6(2.4,-4.8) J7(3.2,-4.8) J8(4,-4.8) J9(4.8,-4.8) J10(5.6,-4.8) J23(16,-4.8) J24(16.8,-4.8) J25(17.6,-4.8) J26(18.4,-4.8) J27(19.2,-4.8) J29(20.4,-4.8) J31(21.2,-4.8) K2(0.4,-5.6) K4(1.2,-5.6) K6(2.4,-5.6) K7(3.2,-5.6) K8(4,-5.6) K9(4.8,-5.6) K10(5.6,-5.6) K23(16,-5.6) K24(16.8,-5.6) K25(17.6,-5.6) K26(18.4,-5.6) K27(19.2,-5.6) K28(20,-5.6) K30(20.8,-5.6) K32(21.6,-5.6) L1(0,-6.4) L3(0.8,-6.4) L5(1.6,-6.4) L6(2.4,-6.4) L27(19.2,-6.4) L29(20.4,-6.4) L31(21.2,-6.4) M2(0.4,-7.2) M4(1.2,-7.2) M6(2.4,-7.2) M27(19.2,-7.2) M28(20,-7.2) M30(20.8,-7.2) M32(21.6,-7.2) N1(0,-8) N3(0.8,-8) N5(1.6,-8) N6(2.4,-8) N27(19.2,-8) N29(20.4,-8) N31(21.2,-8) P2(0.4,-8.8) P4(1.2,-8.8) P6(2.4,-8.8) P27(19.2,-8.8) P28(20,-8.8) P30(20.8,-8.8) P32(21.6,-8.8) R1(0,-9.6) R3(0.8,-9.6) R5(1.6,-9.6) R6(2.4,-9.6) R27(19.2,-9.6) R29(20.4,-9.6) R31(21.2,-9.6) T2(0.4,-10.4) T4(1.2,-10.4) T6(2.4,-10.4) T27(19.2,-10.4) T28(20,-10.4) T30(20.8,-10.4) T32(21.6,-10.4) U1(0,-11.2) U3(0.8,-11.2) U5(1.6,-11.2) U6(2.4,-11.2) U27(19.2,-11.2) U29(20.4,-11.2) U31(21.2,-11.2) V2(0.4,-12) V4(1.2,-12) V6(2.4,-12) V27(19.2,-12) V28(20,-12) V30(20.8,-12) V32(21.6,-12) W1(0,-12.8) W3(0.8,-12.8) W5(1.6,-12.8) W6(2.4,-12.8) W27(19.2,-12.8) W29(20.4,-12.8) W31(21.2,-12.8) Y2(0.4,-13.6) Y4(1.2,-13.6) Y6(2.4,-13.6) Y27(19.2,-13.6) Y28(20,-13.6) Y30(20.8,-13.6) Y32(21.6,-13.6)
  round 0.508 smd: AA11(6.4,-14.2) AA12(7.4,-14.2) AA13(8.4,-14.2) AA15(9.4,-14.2) AA16(10.4,-14.2) AA17(11.2,-14.2) AA18(12.2,-14.2) AA20(13.2,-14.2) AA21(14.2,-14.2) AA22(15.2,-14.2) AB11(6.4,-15.2) AB12(7.4,-15.2) AB13(8.4,-15.2) AB15(9.4,-15.2) AB16(10.4,-15.2) AB17(11.2,-15.2) AB18(12.2,-15.2) AB20(13.2,-15.2) AB21(14.2,-15.2) AB22(15.2,-15.2) L11(6.4,-6.4) L12(7.4,-6.4) L13(8.4,-6.4) L15(9.4,-6.4) L16(10.4,-6.4) L17(11.2,-6.4) L18(12.2,-6.4) L20(13.2,-6.4) L21(14.2,-6.4) L22(15.2,-6.4) M11(6.4,-7.4) M12(7.4,-7.4) M13(8.4,-7.4) M15(9.4,-7.4) M16(10.4,-7.4) M17(11.2,-7.4) M18(12.2,-7.4) M20(13.2,-7.4) M21(14.2,-7.4) M22(15.2,-7.4) N11(6.4,-8.4) N12(7.4,-8.4) N13(8.4,-8.4) N15(9.4,-8.4) N16(10.4,-8.4) N17(11.2,-8.4) N18(12.2,-8.4) N20(13.2,-8.4) N21(14.2,-8.4) N22(15.2,-8.4) R11(6.4,-9.4) R12(7.4,-9.4) R13(8.4,-9.4) R15(9.4,-9.4) R16(10.4,-9.4) R17(11.2,-9.4) R18(12.2,-9.4) R20(13.2,-9.4) R21(14.2,-9.4) R22(15.2,-9.4) T11(6.4,-10.4) T12(7.4,-10.4) T13(8.4,-10.4) T15(9.4,-10.4) T16(10.4,-10.4) T17(11.2,-10.4) T18(12.2,-10.4) T20(13.2,-10.4) T21(14.2,-10.4) T22(15.2,-10.4) U11(6.4,-11.2) U12(7.4,-11.2) U13(8.4,-11.2) U15(9.4,-11.2) U16(10.4,-11.2) U17(11.2,-11.2) U18(12.2,-11.2) U20(13.2,-11.2) U21(14.2,-11.2) U22(15.2,-11.2) V11(6.4,-12.2) V12(7.4,-12.2) V13(8.4,-12.2) V15(9.4,-12.2) V16(10.4,-12.2) V17(11.2,-12.2) V18(12.2,-12.2) V20(13.2,-12.2) V21(14.2,-12.2) V22(15.2,-12.2) Y11(6.4,-13.2) Y12(7.4,-13.2) Y13(8.4,-13.2) Y15(9.4,-13.2) Y16(10.4,-13.2) Y17(11.2,-13.2) Y18(12.2,-13.2) Y20(13.2,-13.2) Y21(14.2,-13.2) Y22(15.2,-13.2)
ACES_50271-0020N-001_2P
  oval 0.787x1.6 smd: 1(0,0) 2(1.25,0)
  rect 2.108x2.997 smd: 3(3.8,-2.9) 4(-2.55,-2.9)
ACES_50278-00401-001_4P
  oval 0.787x1.905 smd: 1(0,0) 2(1.25,0) 3(2.5,0) 4(3.75,0)
  rect 1.295x3.353 smd: 5(-2.85,-4.925) 6(6.6,-4.925)
ACES_50299-00501-003_5P
  round 1.803 hole 1.803 unplated: (-0.2,5.2) (8.2,5.2)
  oval 0.889x2.388 smd: 1(0,0) 2(2,0) 3(4,0) 4(6,0) 5(8,0)
ACES_50524-00401-P01_4P-T
  oval 0.305x1.295 smd: 1(0,0) 2(1,0) 3(2,0) 4(3,0)
  rect 1.803x2.21 smd: 5(-2.65,-5.65) 6(5.65,-5.65)
ACES_51524-0080N-001_8P
  oval 0.61x1.295 smd: 1(0,0) 2(1,0) 3(2,0) 4(3,0) 5(4,0) 6(5,0) 7(6,0) 8(7,0)
  rect 2.489x2.21 smd: 9(10,-3.05) 10(-3,-3.05)
ACES_51524-0100N-001_10P
  oval 0.61x1.295 smd: 1(0,0) 2(1,0) 3(2,0) 4(3,0) 5(4,0) 6(5,0) 7(6,0) 8(7,0) 9(8,0) 10(9,0)
  rect 2.159x2.21 smd: 11(-2.825,-3.05) 12(11.825,-3.05)
ACES_51524-0160N-001_16P
  oval 0.61x1.295 smd: 1(0,0) 2(1,0) 3(2,0) 4(3,0) 5(4,0) 6(5,0) 7(6,0) 8(7,0) 9(8,0) 10(9,0) 11(10,0) 12(11,0) 13(12,0) 14(13,0) 15(14,0) 16(15,0)
  rect 2.159x2.21 smd: 17(-2.825,-3.05) 18(17.825,-3.05)
ACES_88231-03041_3P
  oval 0.787x1.905 smd: 1(0,0) 2(1.25,0) 3(2.5,0)
  rect 1.295x3.353 smd: 4(-2.85,-4.925) 5(5.35,-4.925)
ADM1032ARMZ_MSOP8
  oval 0.381x1.626 smd: 1(0,0) 2(0.65,0) 3(1.3,0) 4(1.95,0) 5(1.95,4.3) 6(1.3,4.3) 7(0.65,4.3) 8(0,4.3)
ALC3234-CG_MQFN48_6X6
  oval 0.203x0.889 smd: 1(0,0) 2(0.4,0) 3(0.8,0) 4(1.2,0) 5(1.6,0) 6(2,0) 7(2.4,0) 8(2.8,0) 9(3.2,0) 10(3.6,0) 11(4,0) 12(4.4,0) 25(4.4,6.1) 26(4,6.1) 27(3.6,6.1) 28(3.2,6.1) 29(2.8,6.1) 30(2.4,6.1) 31(2,6.1) 32(1.6,6.1) 33(1.2,6.1) 34(0.8,6.1) 35(0.4,6.1) 36(0,6.1)
  oval 0.889x0.203 smd: 13(5.25,0.85) 14(5.25,1.25) 15(5.25,1.65) 16(5.25,2.05) 17(5.25,2.45) 18(5.25,2.85) 19(5.25,3.25) 20(5.25,3.65) 21(5.25,4.05) 22(5.25,4.45) 23(5.25,4.85) 24(5.25,5.25) 37(-0.85,5.25) 38(-0.85,4.85) 39(-0.85,4.45) 40(-0.85,4.05) 41(-0.85,3.65) 42(-0.85,3.25) 43(-0.85,2.85) 44(-0.85,2.45) 45(-0.85,2.05) 46(-0.85,1.65) 47(-0.85,1.25) 48(-0.85,0.85)
  rect 4.394x4.394 smd: 49(2.2,3.05)
ALLTO_C144LS-109A9-L_9P-T
  round 1.803 hole 1.194: 1(0,0) 2(2,0) 3(4,0) 4(6,0) 5(8,0) 6(10,0) 7(12,0) 8(14,0) 9(16,0)
  oval 1.6x3.404 hole 0.991x2.794: 10(19.125,0.25) 11(-3.125,0.25)
AO3413_SOT23-3
  oval 1.016x1.524 smd: 1(0,0) 2(0.965,2.083) 3(-0.965,2.083)
AO4407AL_SO8
  oval 0.635x1.854 smd: 1(0,0) 2(1.27,0) 3(2.54,0) 4(3.81,0) 5(3.81,5.165) 6(2.54,5.165) 7(1.27,5.165) 8(0,5.165)
AO4409L_SO8
  oval 0.635x1.854 smd: 1(0,0) 2(1.27,0) 3(2.54,0) 4(3.81,0) 5(3.81,5.165) 6(2.54,5.165) 7(1.27,5.165) 8(0,5.165)
AOZ1336_DFN8_2X2
  oval 0.254x0.787 smd: 1(0,0) 2(0.5,0) 3(1,0) 4(1.5,0) 5(1.5,2.2) 6(1,2.2) 7(0.5,2.2) 8(0,2.2)
  rect 1.499x0.889 smd: 9(0.75,1.1)
AP2301MPG-13_MSOP8
  oval 0.381x1.626 smd: 1(0,0) 2(0.65,0) 3(1.3,0) 4(1.95,0) 5(1.95,4.3) 6(1.3,4.3) 7(0.65,4.3) 8(0,4.3)
  rect 1.803x1.499 smd: 9(0.975,2.15)
APL3512ABI-TRG_SOT23-5
  oval 0.61x1.041 smd: 1(0,0) 2(0.95,0) 3(1.9,0) 4(1.9,2.7) 5(0,2.7)
APL5930KAI-TRG_SO8
  oval 0.635x1.854 smd: 1(0,0) 2(1.27,0) 3(2.54,0) 4(3.81,0) 5(3.81,5.165) 6(2.54,5.165) 7(1.27,5.165) 8(0,5.165)
  rect 2.87x2.489 smd: 9(1.905,2.582)
AZ5125-02SPR7G_SOT23-3
  oval 1.016x1.524 smd: 1(0,0) 2(0.965,2.083) 3(-0.965,2.083)
BAS40CW_SOT323-3
  oval 0.813x0.914 smd: 1(0,0) 2(0.65,1.6) 3(-0.65,1.6)
BAT54C-7-F_SOT23-3
  oval 1.016x1.524 smd: 1(0,0) 2(0.965,2.083) 3(-0.965,2.083)
BAT54CW_SOT323-3
  oval 0.61x0.559 smd: 1(0,0) 2(-0.65,-1.85) 3(0.65,-1.85)
BELLW_80001-1021_204P
  round 1.092 hole 1.092 unplated: (-65.05,-4.1)
  round 1.6 hole 1.6 unplated: (1.75,-4.1)
  oval 0.356x2.007 smd: 1(0,0) 2(-0.3,-8.2) 3(-0.6,0) 4(-0.9,-8.2) 5(-1.2,0) 6(-1.5,-8.2) 7(-1.8,0) 8(-2.1,-8.2) 9(-2.4,0) 10(-2.7,-8.2) 11(-3,0) 12(-3.3,-8.2) 13(-3.6,0) 14(-3.9,-8.2) 15(-4.2,0) 16(-4.5,-8.2) 17(-4.8,0) 18(-5.1,-8.2) 19(-5.4,0) 20(-5.7,-8.2) 21(-6,0) 22(-6.3,-8.2) 23(-6.6,0) 24(-6.9,-8.2) 25(-7.2,0) 26(-7.5,-8.2) 27(-7.8,0) 28(-8.1,-8.2) 29(-8.4,0) 30(-8.7,-8.2) 31(-9,0) 32(-9.3,-8.2) 33(-9.6,0) 34(-9.9,-8.2) 35(-10.2,0) 36(-10.5,-8.2) 37(-10.8,0) 38(-11.1,-8.2) 39(-11.4,0) 40(-11.7,-8.2) 41(-12,0) 42(-12.3,-8.2) 43(-12.6,0) 44(-12.9,-8.2) 45(-13.2,0) 46(-13.5,-8.2) 47(-13.8,0) 48(-14.1,-8.2) 49(-14.4,0) 50(-14.7,-8.2) 51(-15,0) 52(-15.3,-8.2) 53(-15.6,0) 54(-15.9,-8.2) 55(-16.2,0) 56(-16.5,-8.2) 57(-16.8,0) 58(-17.1,-8.2) 59(-17.4,0) 60(-17.7,-8.2) 61(-18,0) 62(-18.3,-8.2) 63(-18.6,0) 64(-18.9,-8.2) 65(-19.2,0) 66(-19.5,-8.2) 67(-19.8,0) 68(-20.1,-8.2) 69(-20.4,0) 70(-20.7,-8.2) 71(-21,0) 72(-21.3,-8.2) 73(-24,0) 74(-24.3,-8.2) 75(-24.6,0) 76(-24.9,-8.2) 77(-25.2,0) 78(-25.5,-8.2) 79(-25.8,0) 80(-26.1,-8.2) 81(-26.4,0) 82(-26.7,-8.2) 83(-27,0) 84(-27.3,-8.2) 85(-27.6,0) 86(-27.9,-8.2) 87(-28.2,0) 88(-28.5,-8.2) 89(-28.8,0) 90(-29.1,-8.2) 91(-29.4,0) 92(-29.7,-8.2) 93(-30,0) 94(-30.3,-8.2) 95(-30.6,0) 96(-30.9,-8.2) 97(-31.2,0) 98(-31.5,-8.2) 99(-31.8,0) 100(-32.1,-8.2) 101(-32.4,0) 102(-32.7,-8.2) 103(-33,0) 104(-33.3,-8.2) 105(-33.6,0) 106(-33.9,-8.2) 107(-34.2,0) 108(-34.5,-8.2) 109(-34.8,0) 110(-35.1,-8.2) 111(-35.4,0) 112(-35.7,-8.2) 113(-36,0) 114(-36.3,-8.2) 115(-36.6,0) 116(-36.9,-8.2) 117(-37.2,0) 118(-37.5,-8.2) 119(-37.8,0) 120(-38.1,-8.2) 121(-38.4,0) 122(-38.7,-8.2) 123(-39,0) 124(-39.3,-8.2) 125(-39.6,0) 126(-39.9,-8.2) 127(-40.2,0) 128(-40.5,-8.2) 129(-40.8,0) 130(-41.1,-8.2) 131(-41.4,0) 132(-41.7,-8.2) 133(-42,0) 134(-42.3,-8.2) 135(-42.6,0) 136(-42.9,-8.2) 137(-43.2,0) 138(-43.5,-8.2) 139(-43.8,0) 140(-44.1,-8.2) 141(-44.4,0) 142(-44.7,-8.2) 143(-45,0) 144(-45.3,-8.2) 145(-45.6,0) 146(-45.9,-8.2) 147(-46.2,0) 148(-46.5,-8.2) 149(-46.8,0) 150(-47.1,-8.2) 151(-47.4,0) 152(-47.7,-8.2) 153(-48,0) 154(-48.3,-8.2) 155(-48.6,0) 156(-48.9,-8.2) 157(-49.2,0) 158(-49.5,-8.2) 159(-49.8,0) 160(-50.1,-8.2) 161(-50.4,0) 162(-50.7,-8.2) 163(-51,0) 164(-51.3,-8.2) 165(-51.6,0) 166(-51.9,-8.2) 167(-52.2,0) 168(-52.5,-8.2) 169(-52.8,0) 170(-53.1,-8.2) 171(-53.4,0) 172(-53.7,-8.2) 173(-54,0) 174(-54.3,-8.2) 175(-54.6,0) 176(-54.9,-8.2) 177(-55.2,0) 178(-55.5,-8.2) 179(-55.8,0) 180(-56.1,-8.2) 181(-56.4,0) 182(-56.7,-8.2) 183(-57,0) 184(-57.3,-8.2) 185(-57.6,0) 186(-57.9,-8.2) 187(-58.2,0) 188(-58.5,-8.2) 189(-58.8,0) 190(-59.1,-8.2) 191(-59.4,0) 192(-59.7,-8.2) 193(-60,0) 194(-60.3,-8.2) 195(-60.6,0) 196(-60.9,-8.2) 197(-61.2,0) 198(-61.5,-8.2) 199(-61.8,0) 200(-62.1,-8.2) 201(-62.4,0) 202(-62.7,-8.2) 203(-63,0) 204(-63.3,-8.2)
  rect 3.505x4.597 smd: 205(1.15,7.9) 206(-64.45,7.9)
BELLW_80011-1021_204P
  round 1.6 hole 1.6 unplated: (-1.75,4.1)
  round 1.092 hole 1.092 unplated: (65.05,4.1)
  oval 0.356x2.007 smd: 1(0,0) 2(0.3,8.2) 3(0.6,0) 4(0.9,8.2) 5(1.2,0) 6(1.5,8.2) 7(1.8,0) 8(2.1,8.2) 9(2.4,0) 10(2.7,8.2) 11(3,0) 12(3.3,8.2) 13(3.6,0) 14(3.9,8.2) 15(4.2,0) 16(4.5,8.2) 17(4.8,0) 18(5.1,8.2) 19(5.4,0) 20(5.7,8.2) 21(6,0) 22(6.3,8.2) 23(6.6,0) 24(6.9,8.2) 25(7.2,0) 26(7.5,8.2) 27(7.8,0) 28(8.1,8.2) 29(8.4,0) 30(8.7,8.2) 31(9,0) 32(9.3,8.2) 33(9.6,0) 34(9.9,8.2) 35(10.2,0) 36(10.5,8.2) 37(10.8,0) 38(11.1,8.2) 39(11.4,0) 40(11.7,8.2) 41(12,0) 42(12.3,8.2) 43(12.6,0) 44(12.9,8.2) 45(13.2,0) 46(13.5,8.2) 47(13.8,0) 48(14.1,8.2) 49(14.4,0) 50(14.7,8.2) 51(15,0) 52(15.3,8.2) 53(15.6,0) 54(15.9,8.2) 55(16.2,0) 56(16.5,8.2) 57(16.8,0) 58(17.1,8.2) 59(17.4,0) 60(17.7,8.2) 61(18,0) 62(18.3,8.2) 63(18.6,0) 64(18.9,8.2) 65(19.2,0) 66(19.5,8.2) 67(19.8,0) 68(20.1,8.2) 69(20.4,0) 70(20.7,8.2) 71(21,0) 72(21.3,8.2) 73(24,0) 74(24.3,8.2) 75(24.6,0) 76(24.9,8.2) 77(25.2,0) 78(25.5,8.2) 79(25.8,0) 80(26.1,8.2) 81(26.4,0) 82(26.7,8.2) 83(27,0) 84(27.3,8.2) 85(27.6,0) 86(27.9,8.2) 87(28.2,0) 88(28.5,8.2) 89(28.8,0) 90(29.1,8.2) 91(29.4,0) 92(29.7,8.2) 93(30,0) 94(30.3,8.2) 95(30.6,0) 96(30.9,8.2) 97(31.2,0) 98(31.5,8.2) 99(31.8,0) 100(32.1,8.2) 101(32.4,0) 102(32.7,8.2) 103(33,0) 104(33.3,8.2) 105(33.6,0) 106(33.9,8.2) 107(34.2,0) 108(34.5,8.2) 109(34.8,0) 110(35.1,8.2) 111(35.4,0) 112(35.7,8.2) 113(36,0) 114(36.3,8.2) 115(36.6,0) 116(36.9,8.2) 117(37.2,0) 118(37.5,8.2) 119(37.8,0) 120(38.1,8.2) 121(38.4,0) 122(38.7,8.2) 123(39,0) 124(39.3,8.2) 125(39.6,0) 126(39.9,8.2) 127(40.2,0) 128(40.5,8.2) 129(40.8,0) 130(41.1,8.2) 131(41.4,0) 132(41.7,8.2) 133(42,0) 134(42.3,8.2) 135(42.6,0) 136(42.9,8.2) 137(43.2,0) 138(43.5,8.2) 139(43.8,0) 140(44.1,8.2) 141(44.4,0) 142(44.7,8.2) 143(45,0) 144(45.3,8.2) 145(45.6,0) 146(45.9,8.2) 147(46.2,0) 148(46.5,8.2) 149(46.8,0) 150(47.1,8.2) 151(47.4,0) 152(47.7,8.2) 153(48,0) 154(48.3,8.2) 155(48.6,0) 156(48.9,8.2) 157(49.2,0) 158(49.5,8.2) 159(49.8,0) 160(50.1,8.2) 161(50.4,0) 162(50.7,8.2) 163(51,0) 164(51.3,8.2) 165(51.6,0) 166(51.9,8.2) 167(52.2,0) 168(52.5,8.2) 169(52.8,0) 170(53.1,8.2) 171(53.4,0) 172(53.7,8.2) 173(54,0) 174(54.3,8.2) 175(54.6,0) 176(54.9,8.2) 177(55.2,0) 178(55.5,8.2) 179(55.8,0) 180(56.1,8.2) 181(56.4,0) 182(56.7,8.2) 183(57,0) 184(57.3,8.2) 185(57.6,0) 186(57.9,8.2) 187(58.2,0) 188(58.5,8.2) 189(58.8,0) 190(59.1,8.2) 191(59.4,0) 192(59.7,8.2) 193(60,0) 194(60.3,8.2) 195(60.6,0) 196(60.9,8.2) 197(61.2,0) 198(61.5,8.2) 199(61.8,0) 200(62.1,8.2) 201(62.4,0) 202(62.7,8.2) 203(63,0) 204(63.3,8.2)
  rect 3.505x4.597 smd: 205(-1.15,16.1) 206(64.45,16.1)
BSS138-G_SOT23-3
  oval 1.016x1.524 smd: 1(0,0) 2(0.965,2.083) 3(-0.965,2.083)
C_0402
  rect 0.508x0.559 smd: 1(0,0) 2(0.914,0)
C_0603
  rect 0.635x0.889 smd: 1(0,0) 2(1.397,0)
C_0805
  rect 0.813x1.397 smd: 1(0,0) 2(1.702,0)
C_1206
  rect 1.016x1.651 smd: 1(0,0) 2(2.667,0)
C_D2
  rect 2.388x2.794 smd: 1(0,0) 2(6.4,0)
C_D3
  rect 2.388x2.794 smd: 1(0,0) 2(6.4,0)
C_EEEFZ1E101P
  oval 3.2x1.6 smd: 1(0,0) 2(5,0)
C_MP6VLPS220MC4R2
  oval 3.505x1.6 smd: 1(0,0) 2(-5.6,0)
C_MP6VU330MC6
  oval 3.505x1.6 smd: 1(0,0) 2(5.6,0)
CONCR_099ATAC19NBLCNF_19P
  round 0.813 hole 0.559: 1(0,0) 2(0.5,1.55) 3(1,0) 4(1.5,1.55) 5(2,0) 6(2.5,1.55) 7(3,0) 8(3.5,1.55) 9(4,0) 10(4.5,1.55) 11(5,0) 12(5.5,1.55) 13(6,0) 14(6.5,1.55) 15(7,0) 16(7.5,1.55) 17(8,0) 18(8.5,1.55) 19(9,0)
  oval 1.499x2.21 hole 0.889x1.6: 20(-2.75,1.7) 21(-4.65,-6.5) 22(11.75,1.7) 23(13.65,-7.75)
CSD86350Q5D_SON8
  oval 2.032x0.889 smd: 1(0,0)
  oval 0.711x0.889 smd: 2(1.98,0) 3(3.3,0) 4(3.3,5.39) 5(1.98,5.39) 6(0.66,5.39) 7(-0.66,5.39)
  custom 0.883x0.883 smd: 8(1.32,2.695)
CYNTE_PCMB053T-1R0MS_2P-S
  rect 1.905x2.794 smd: 1(0,0) 2(4.1,0)
CYNTE_PCMB104T-1R0MH_2P
  rect 3.81x3.988 smd: 1(0,0) 2(9.2,0)
DMN66D0LDW-7_SOT363-6
  oval 0.432x0.61 smd: 1(0,0) 2(0.65,0) 3(1.3,0) 4(1.3,1.9) 5(0.65,1.9) 6(0,1.9)
E-T_4260K-F10N-00L_10P
  oval 0.508x0.991 smd: 1(0,0) 2(-0.8,0) 3(-1.6,0) 4(-2.4,0) 5(-3.2,0) 6(-4,0) 7(-4.8,0) 8(-5.6,0) 9(-6.4,0) 10(-7.2,0)
  rect 1.194x1.702 smd: 11(1.3,-1.95) 12(-8.5,-1.95)
EMC1403-2-AIZL-TR_MSOP10
  oval 0.254x1.626 smd: 1(0,0) 2(0.5,0) 3(1,0) 4(1.5,0) 5(2,0) 6(2,4.3) 7(1.5,4.3) 8(1,4.3) 9(0.5,4.3) 10(0,4.3)
F_1206L150PR
  rect 0.991x1.803 smd: 1(0,0) 2(2.8,0)
F_1812L075-24DR
  rect 0.889x3.15 smd: 1(0,0) 2(4.35,0)
FDV301N_NL_SOT23-3
  oval 1.016x1.524 smd: 1(0,0) 2(0.965,2.083) 3(-0.965,2.083)
FIDUCIAL_C40M80
  round 1.016 smd: 1(0,0)
G993P1UF_SOP8
  oval 0.635x1.854 smd: 1(0,0) 2(1.27,0) 3(2.54,0) 4(3.81,0) 5(3.81,5.165) 6(2.54,5.165) 7(1.27,5.165) 8(0,5.165)
H_2P8
  round 3.302 hole 2.794: 1(0,0)
H_2P8N
  round 2.794 hole 2.794 unplated: (0,0)
H_2P8X3P3N
  oval 2.794x3.302 hole 2.794x3.302 unplated: (0,0)
H_2P8X4P8N
  oval 2.794x4.801 hole 2.794x4.801 unplated: (0,0)
H_3P0
  round 3.505 hole 2.997: 1(0,0)
H_3P3
  round 3.81 hole 3.302: 1(0,0)
H_3P6
  round 4.115 hole 3.607: 1(0,0)
HASWELL-MCP-E-ULT_BGA_1168P-T
  round 0.508 smd: A3(-1.137,0) A62(-38.036,0) AW1(0,22.042) AW63(-38.628,22.057) AY2(-0.543,22.628) AY62(-38.062,22.628) B2(-0.508,0.508) B63(-38.628,0.592) C1(0,1.137)
  round 0.381 smd: A4(-1.894,0) A5(-2.554,0) A6(-3.75,0) A59(-35.9,0) A60(-36.726,0) A61(-37.386,0) AA9(-5.032,11.576) AA21(-11.688,11.489) AA23(-13.115,11.489) AA58(-35.377,11.33) AB10(-5.476,12.053) AB20(-11.18,11.896) AB21(-11.688,12.302) AB22(-12.607,11.896) AB23(-13.115,12.302) AB57(-35.057,11.98) AC9(-5.032,12.529) AC20(-11.18,12.709) AC22(-12.607,12.709) AC58(-35.377,12.63) AD10(-5.476,13.005) AD21(-11.688,13.115) AD23(-13.115,13.115) AD57(-35.057,13.28) AE9(-5.032,13.481) AE10(-5.476,13.958) AE20(-11.18,13.521) AE21(-11.688,13.928) AE22(-12.607,13.521) AE23(-13.115,13.928) AE58(-35.377,13.931) AF9(-5.032,14.434) AF11(-6.059,14.282) AF12(-6.872,14.282) AF14(-7.685,14.282) AF15(-8.497,14.282) AF17(-9.31,14.282) AF18(-10.123,14.282) AF20(-10.936,14.282) AF22(-12.607,14.334) AG10(-5.653,14.79) AG11(-6.465,14.79) AG13(-7.278,14.79) AG14(-8.091,14.79) AG16(-8.904,14.79) AG17(-9.717,14.79) AG19(-10.529,14.79) AG20(-11.342,14.79) AG23(-13.115,14.741) AG57(-35.057,14.581) AG58(-35.692,15.009) AH22(-12.607,15.147) AH24(-13.92,15.289) AH26(-15.22,15.289) AH28(-16.521,15.289) AH30(-17.821,15.289) AH32(-19.122,15.289) AH34(-20.422,15.289) AH36(-21.723,15.289) AH38(-23.023,15.289) AH40(-24.324,15.289) AH42(-25.624,15.289) AH44(-26.925,15.289) AH46(-28.225,15.289) AH49(-29.526,15.289) AH51(-30.826,15.289) AH53(-32.127,15.289) AH55(-33.427,15.289) AH57(-34.728,15.289) AJ23(-13.115,15.553) AJ25(-14.57,15.614) AJ27(-15.871,15.614) AJ29(-17.171,15.614) AJ31(-18.472,15.614) AJ33(-19.772,15.614) AJ35(-21.073,15.614) AJ37(-22.373,15.614) AJ39(-23.674,15.614) AJ41(-24.974,15.614) AJ43(-26.275,15.614) AJ45(-27.575,15.614) AJ47(-28.875,15.614) AJ50(-30.176,15.614) AJ52(-31.476,15.614) AJ54(-32.777,15.614) AJ56(-34.077,15.614) AJ58(-35.378,15.614) AT1(0,19.997) AT63(-38.628,19.848) AU1(0,20.657) AU63(-38.628,20.673) AV1(0,21.318) AV2(-0.66,21.308) AV62(-37.978,21.318) AV63(-38.628,21.333) AW2(-0.66,21.968) AW3(-1.321,21.968) AW61(-37.328,21.978) AW62(-37.978,21.978) AY3(-1.267,22.628) AY4(-1.928,22.628) AY5(-2.588,22.628) AY59(-36.088,22.628) AY60(-36.748,22.628) AY61(-37.409,22.628) B3(-1.259,0.65) B61(-37.315,0.66) B62(-37.978,0.724) C2(-0.65,1.259) C62(-37.978,1.384) C63(-38.628,1.316) D1(0,1.861) D63(-38.628,1.976) E1(0,2.522) E23(-13.333,2.601) E25(-14.714,2.601) E27(-15.84,2.601) E29(-17.221,2.601) E31(-18.348,2.601) E33(-19.729,2.601) E35(-20.855,2.601) E37(-22.236,2.601) E39(-23.363,2.601) E41(-24.744,2.601) E43(-25.87,2.601) E45(-27.251,2.601) E47(-28.378,2.601) E49(-29.759,2.601) E51(-30.885,2.601) E53(-32.266,2.601) E55(-33.393,2.601) E57(-34.774,2.601) E63(-38.628,2.647) F1(0,3.436) F22(-12.717,3.058) F24(-14.023,3.126) F26(-15.277,3.126) F28(-16.531,3.126) F30(-17.785,3.126) F32(-19.038,3.126) F34(-20.292,3.126) F36(-21.546,3.126) F38(-22.8,3.126) F40(-24.053,3.126) F42(-25.307,3.126) F44(-26.561,3.126) F46(-27.815,3.126) F48(-29.068,3.126) F50(-30.322,3.126) F52(-31.576,3.126) F54(-32.83,3.126) F56(-34.083,3.126) F58(-35.377,3.126) G22(-12.607,3.768) G23(-13.333,3.451) G25(-14.714,3.451) G27(-15.84,3.451) G29(-17.221,3.451) G31(-18.348,3.451) G33(-19.729,3.451) G35(-20.855,3.451) G37(-22.236,3.451) G39(-23.363,3.451) G41(-24.744,3.451) G43(-25.87,3.451) G45(-27.251,3.451) G47(-28.378,3.451) G49(-29.759,3.451) G51(-30.885,3.451) G53(-32.266,3.451) G55(-33.393,3.451) G57(-34.774,3.451) H22(-12.607,4.581) H23(-13.115,4.174) H57(-35.057,4.101) J22(-12.607,5.393) J23(-13.115,4.987) J58(-35.377,4.827) K9(-5.032,5.861) K10(-5.935,5.7) K12(-6.888,5.7) K14(-7.84,5.7) K16(-8.793,5.7) K18(-9.745,5.7) K19(-10.698,5.7) K21(-11.65,5.7) K23(-13.115,5.8) K57(-35.057,5.478) L10(-5.476,6.338) L11(-6.412,6.144) L13(-7.364,6.144) L15(-8.317,6.144) L17(-9.269,6.144) L18(-10.222,6.144) L20(-11.18,6.206) L22(-12.607,6.206) L58(-35.377,6.128) M9(-5.032,6.814) M20(-11.18,7.019) M21(-11.688,6.613) M22(-12.607,7.019) M23(-13.115,6.613) M57(-35.057,6.778) N10(-5.476,7.29) N21(-11.688,7.425) N23(-13.115,7.425) N58(-35.377,7.428) P9(-5.032,7.766) P20(-11.18,7.832) P22(-12.607,7.832) P57(-35.057,8.078) R10(-5.476,8.243) R20(-11.18,8.645) R21(-11.688,8.238) R22(-12.607,8.645) R23(-13.115,8.238) T9(-5.032,8.719) T21(-11.688,9.051) T23(-13.115,9.051) T58(-35.377,8.729) U9(-5.032,9.671) U10(-5.476,9.195) U20(-11.18,9.457) U22(-12.607,9.457) U57(-35.057,9.379) V10(-5.476,10.148) V21(-11.688,9.864) V23(-13.115,9.864) V58(-35.377,10.029) W9(-5.032,10.624) W20(-11.18,10.27) W21(-11.688,10.677) W22(-12.607,10.27) W23(-13.115,10.677) W57(-35.057,10.679) Y10(-5.476,11.1) Y20(-11.18,11.083) Y22(-12.607,11.083)
  round 0.305 smd: A8(-4.538,0) A9(-5.452,0) A11(-6.367,0) A12(-7.116,0) A14(-8.03,0) A15(-8.945,0) A17(-9.694,0) A18(-10.608,0) A20(-11.523,0) A21(-12.272,0) A23(-13.186,0) A24(-14.023,0.325) A25(-14.714,0) A27(-15.84,0) A28(-16.531,0.325) A29(-17.221,0) A31(-18.348,0) A32(-19.038,0.325) A33(-19.729,0) A35(-20.855,0) A36(-21.546,0.325) A37(-22.236,0) A39(-23.363,0) A40(-24.053,0.325) A41(-24.744,0) A43(-25.87,0) A44(-26.561,0.325) A45(-27.251,0) A47(-28.378,0) A48(-29.068,0.325) A49(-29.759,0) A51(-30.885,0) A52(-31.576,0.325) A53(-32.266,0) A55(-33.393,0) A56(-34.083,0.325) A57(-34.774,0) AA1(0,11.717) AA2(-0.65,11.717) AA3(-1.3,11.678) AA4(-1.951,11.678) AA59(-36.027,11.638) AA60(-36.678,11.638) AA61(-37.328,11.638) AA62(-37.978,11.676) AA63(-38.628,11.676) AB5(-2.637,12.053) AB6(-3.287,12.053) AB7(-3.937,12.053) AB8(-4.587,12.053) AC1(0,12.466) AC2(-0.65,12.466) AC3(-1.3,12.504) AC4(-1.951,12.504) AC59(-36.027,12.464) AC60(-36.678,12.464) AC61(-37.328,12.464) AC62(-37.978,12.426) AC63(-38.628,12.426) AD1(0,13.215) AD2(-0.65,13.215) AD3(-1.3,13.177) AD4(-1.951,13.177) AD5(-2.637,13.005) AD6(-3.287,13.005) AD7(-3.937,13.005) AD8(-4.587,13.005) AD59(-36.027,13.137) AD60(-36.678,13.137) AD61(-37.328,13.137) AD62(-37.978,13.175) AD63(-38.628,13.175) AE5(-2.637,13.958) AE6(-3.287,13.958) AE7(-3.937,13.958) AE8(-4.587,13.958) AE59(-36.027,13.962) AE60(-36.678,13.962) AE61(-37.328,13.962) AE62(-37.978,13.924) AE63(-38.628,13.924) AF1(0,13.964) AF2(-0.65,13.964) AF3(-1.3,14.003) AF4(-1.951,14.003) AG1(0,14.714) AG2(-0.65,14.714) AG3(-1.3,14.676) AG4(-1.951,14.676) AG5(-2.637,14.91) AG6(-3.287,14.91) AG7(-3.937,14.91) AG8(-4.587,14.91) AG21(-11.955,15.122) AG60(-36.352,14.602) AG61(-37.003,14.602) AG62(-37.653,14.602) AG63(-38.303,14.602) AH1(0,15.463) AH2(-0.65,15.463) AH3(-1.3,15.501) AH4(-1.951,15.501) AH10(-5.653,15.476) AH11(-6.465,15.476) AH13(-7.278,15.476) AH14(-8.091,15.476) AH16(-8.904,15.476) AH17(-9.717,15.476) AH19(-10.529,15.476) AH20(-11.342,15.476) AH60(-36.678,15.278) AH61(-37.328,15.278) AH62(-37.978,15.278) AH63(-38.628,15.278) AJ5(-2.637,15.863) AJ6(-3.287,15.863) AJ7(-3.937,15.863) AJ8(-4.587,15.863) AJ10(-5.653,16.126) AJ11(-6.465,16.126) AJ13(-7.278,16.126) AJ14(-8.091,16.126) AJ60(-36.352,15.954) AJ61(-37.003,15.954) AJ62(-37.653,15.954) AJ63(-38.303,15.954) AK1(0,16.212) AK2(-0.65,16.212) AK3(-1.3,16.174) AK4(-1.951,16.174) AK8(-4.303,16.451) AK18(-9.848,16.266) AK20(-10.801,16.266) AK21(-11.753,16.266) AK60(-36.678,16.523) AK61(-37.328,16.523) AK62(-37.978,16.629) AK63(-38.628,16.629) AL1(0,16.962) AL2(-0.65,16.962) AL3(-1.3,17) AL4(-1.951,17) AL5(-2.901,16.776) AL7(-3.739,16.776) AL8(-4.303,17.101) AL10(-5.658,16.776) AL11(-6.221,17.101) AL13(-7.576,16.776) AL15(-8.14,17.101) AL17(-9.222,16.583) AL18(-9.848,16.916) AL20(-10.801,16.916) AL21(-11.753,16.916) AL22(-12.706,16.916) AL23(-13.529,16.916) AL25(-14.504,16.916) AL26(-15.456,16.916) AL28(-16.409,16.916) AL29(-17.361,16.916) AL31(-18.26,16.591) AL32(-18.824,16.916) AL33(-19.726,16.916) AL35(-20.729,16.916) AL36(-21.58,16.916) AL38(-22.634,16.916) AL39(-23.542,16.591) AL40(-24.131,16.916) AL42(-24.944,16.916) AL43(-25.897,16.916) AL45(-26.874,16.916) AL46(-27.802,16.916) AL48(-28.856,16.916) AL49(-29.757,16.916) AL51(-30.761,16.916) AL52(-31.583,16.916) AL54(-32.61,16.916) AL55(-33.562,16.916) AL57(-34.509,16.916) AL58(-35.408,16.916) AL60(-36.352,17.169) AL61(-37.003,17.169) AM1(0,17.711) AM2(-0.65,17.711) AM3(-1.3,17.673) AM4(-1.951,17.673) AM5(-2.901,17.426) AM7(-3.739,17.426) AM8(-4.303,17.752) AM10(-5.658,17.426) AM11(-6.221,17.752) AM13(-7.576,17.426) AM15(-8.14,17.752) AM17(-9.222,17.233) AM18(-9.848,17.567) AM20(-10.801,17.567) AM21(-11.753,17.567) AM22(-12.706,17.567) AM23(-13.529,17.567) AM25(-14.504,17.567) AM26(-15.456,17.567) AM28(-16.409,17.567) AM29(-17.361,17.567) AM31(-18.26,17.242) AM32(-18.824,17.567) AM33(-19.726,17.567) AM35(-20.729,17.567) AM36(-21.58,17.567) AM38(-22.634,17.567) AM40(-24.131,17.567) AM42(-24.944,17.567) AM43(-25.897,17.567) AM45(-26.874,17.567) AM46(-27.802,17.567) AM48(-28.856,17.567) AM49(-29.757,17.567) AM51(-30.761,17.567) AM52(-31.583,17.567) AM54(-32.61,17.567) AM55(-33.562,17.567) AM57(-34.509,17.567) AM58(-35.408,17.567) AM60(-36.678,17.816) AM61(-37.328,17.816) AM62(-37.978,17.709) AM63(-38.628,17.709) AN1(0,18.46) AN2(-0.65,18.46) AN3(-1.3,18.498) AN4(-1.951,18.498) AN5(-2.901,18.077) AN7(-3.739,18.077) AN8(-4.303,18.402) AN10(-5.658,18.077) AN11(-6.221,18.402) AN13(-7.576,18.077) AN15(-8.14,18.402) AN17(-9.222,17.883) AN18(-9.848,18.217) AN20(-10.801,18.217) AN21(-11.753,18.217) AN22(-12.706,18.217) AN23(-13.529,18.217) AN25(-14.504,18.217) AN26(-15.456,18.217) AN28(-16.409,18.217) AN29(-17.361,18.217) AN31(-18.26,17.892) AN32(-18.824,18.217) AN33(-19.726,18.217) AN35(-20.729,18.217) AN36(-21.58,18.217) AN38(-22.634,18.217) AN39(-23.542,17.892) AN40(-24.131,18.217) AN42(-24.944,18.217) AN43(-25.897,18.217) AN45(-26.874,18.217) AN46(-27.802,18.217) AN48(-28.856,18.217) AN49(-29.757,18.217) AN51(-30.761,18.217) AN52(-31.583,18.217) AN54(-32.61,18.217) AN55(-33.562,18.217) AN57(-34.509,18.217) AN58(-35.408,18.217) AN60(-36.352,18.385) AN61(-37.003,18.385) AN62(-37.653,18.385) AN63(-38.303,18.385) AP1(0,19.21) AP2(-0.65,19.21) AP3(-1.3,19.171) AP4(-1.951,19.171) AP5(-2.901,18.727) AP7(-3.739,18.727) AP8(-4.303,19.052) AP10(-5.658,18.727) AP11(-6.221,19.052) AP13(-7.576,18.727) AP15(-8.14,19.052) AP17(-9.222,18.533) AP18(-9.848,18.867) AP20(-10.801,18.867) AP21(-11.753,18.867) AP22(-12.706,18.867) AP23(-13.529,18.867) AP25(-14.504,18.867) AP26(-15.456,18.867) AP28(-16.409,18.867) AP29(-17.361,18.867) AP31(-18.26,18.542) AP32(-18.824,18.867) AP33(-19.726,18.867) AP35(-20.729,18.867) AP36(-21.58,18.867) AP38(-22.634,18.867) AP39(-23.542,18.542) AP40(-24.131,18.867) AP42(-24.944,18.867) AP43(-25.897,18.867) AP45(-26.874,18.867) AP46(-27.802,18.867) AP48(-28.856,18.867) AP49(-29.757,18.867) AP51(-30.761,18.867) AP52(-31.583,18.867) AP54(-32.61,18.867) AP55(-33.562,18.867) AP57(-34.509,18.867) AP58(-35.408,18.867) AP60(-36.678,19.06) AP61(-37.328,19.06) AP62(-37.978,19.06) AP63(-38.628,19.06) AR5(-2.901,19.377) AR7(-3.739,19.377) AR8(-4.303,19.702) AR10(-5.658,19.377) AR11(-6.221,19.702) AR13(-7.576,19.377) AR15(-8.14,19.702) AR17(-9.222,19.184) AR18(-9.848,19.517) AR20(-10.801,19.517) AR21(-11.753,19.517) AR22(-12.706,19.517) AR23(-13.529,19.517) AR25(-14.504,19.517) AR26(-15.456,19.517) AR28(-16.409,19.517) AR29(-17.361,19.517) AR31(-18.26,19.192) AR32(-18.824,19.517) AR33(-19.726,19.517) AR35(-20.729,19.517) AR36(-21.58,19.517) AR38(-22.634,19.517) AR39(-23.542,19.192) AR40(-24.131,19.517) AR42(-24.944,19.517) AR43(-25.897,19.517) AR45(-26.874,19.517) AR46(-27.802,19.517) AR48(-28.856,19.517) AR49(-29.757,19.517) AR51(-30.761,19.517) AR52(-31.583,19.517) AR54(-32.61,19.517) AR55(-33.562,19.517) AR57(-34.509,19.517) AR58(-35.408,19.517) AT2(-0.65,19.959) AT3(-1.3,19.997) AT4(-1.951,19.997) AT5(-2.901,20.027) AT7(-3.739,20.027) AT10(-5.658,20.027) AT13(-7.576,20.027) AT35(-20.437,20.22) AT37(-22.011,20.22) AT40(-23.586,20.22) AT42(-25.161,20.22) AT43(-26.736,20.22) AT46(-28.311,20.22) AT49(-29.912,20.248) AT61(-37.003,19.634) AT62(-37.812,19.69) AU2(-0.655,20.647) AU3(-1.315,20.647) AU4(-1.976,20.647) AU6(-3.337,20.678) AU7(-4.163,20.678) AU8(-4.836,20.678) AU10(-5.661,20.678) AU11(-6.335,20.678) AU12(-7.16,20.678) AU14(-7.833,20.678) AU15(-8.659,20.678) AU16(-9.222,20.353) AU17(-9.86,20.678) AU18(-10.536,20.353) AU19(-11.105,20.678) AU20(-11.751,20.353) AU21(-12.397,20.678) AU22(-12.966,20.353) AU23(-13.642,20.678) AU24(-14.318,20.353) AU25(-14.993,20.678) AU26(-15.669,20.353) AU27(-16.238,20.678) AU28(-16.884,20.353) AU29(-17.531,20.678) AU30(-18.1,20.353) AU31(-18.775,20.678) AU33(-19.372,20.33) AU34(-19.974,20.678) AU35(-20.899,20.678) AU36(-21.549,20.678) AU37(-22.474,20.678) AU39(-23.124,20.678) AU40(-24.048,20.678) AU41(-24.699,20.678) AU42(-25.623,20.678) AU43(-26.274,20.678) AU44(-27.198,20.678) AU46(-27.848,20.678) AU47(-28.773,20.678) AU49(-29.423,20.678) AU50(-30.4,20.678) AU51(-30.98,20.353) AU52(-31.656,20.678) AU53(-32.331,20.353) AU54(-32.9,20.678) AU55(-33.547,20.353) AU56(-34.193,20.678) AU57(-34.762,20.353) AU58(-35.438,20.678) AU59(-36.002,20.353) AU60(-36.566,20.678) AU61(-37.277,20.401) AU62(-37.978,20.663) AV3(-1.321,21.308) AV4(-1.976,21.308) AV5(-2.664,21.328) AV6(-3.337,21.328) AV7(-4.163,21.328) AV8(-4.836,21.328) AV10(-5.661,21.328) AV11(-6.335,21.328) AV12(-7.16,21.328) AV14(-7.833,21.328) AV15(-8.659,21.328) AV16(-9.222,21.003) AV17(-9.86,21.328) AV18(-10.536,21.003) AV19(-11.105,21.328) AV20(-11.751,21.003) AV21(-12.397,21.328) AV22(-12.966,21.003) AV23(-13.642,21.328) AV24(-14.318,21.003) AV25(-14.993,21.328) AV26(-15.669,21.003) AV27(-16.238,21.328) AV28(-16.884,21.003) AV29(-17.531,21.328) AV30(-18.1,21.003) AV31(-18.775,21.328) AV33(-19.4,21.003) AV34(-20.024,21.328) AV35(-20.849,21.328) AV36(-21.599,21.328) AV37(-22.424,21.328) AV39(-23.173,21.328) AV40(-23.999,21.328) AV41(-24.748,21.328) AV42(-25.574,21.328) AV43(-26.323,21.328) AV44(-27.149,21.328) AV46(-27.898,21.328) AV47(-28.723,21.328) AV49(-29.473,21.328) AV50(-30.298,21.328) AV51(-30.98,21.003) AV52(-31.656,21.328) AV53(-32.331,21.003) AV54(-32.9,21.328) AV55(-33.547,21.003) AV56(-34.193,21.328) AV57(-34.762,21.003) AV58(-35.438,21.328) AV59(-36.002,21.003) AV60(-36.566,21.328) AV61(-37.302,21.051) AW4(-1.976,21.968) AW5(-2.626,21.978) AW6(-3.375,21.978) AW7(-4.125,21.978) AW8(-4.874,21.978) AW10(-5.623,21.978) AW11(-6.373,21.978) AW12(-7.122,21.978) AW14(-7.871,21.978) AW15(-8.621,21.978) AW16(-9.222,21.653) AW17(-9.86,21.978) AW18(-10.536,21.653) AW19(-11.211,21.978) AW21(-12.291,21.978) AW22(-12.966,21.653) AW23(-13.642,21.978) AW24(-14.318,21.653) AW25(-14.993,21.978) AW26(-15.669,21.653) AW27(-16.345,21.978) AW29(-17.424,21.978) AW30(-18.1,21.653) AW31(-18.775,21.978) AW33(-19.451,21.653) AW34(-20.024,21.978) AW35(-20.849,21.978) AW36(-21.599,21.978) AW37(-22.424,21.978) AW39(-23.173,21.978) AW40(-23.999,21.978) AW41(-24.748,21.978) AW42(-25.574,21.978) AW43(-26.323,21.978) AW44(-27.149,21.978) AW46(-27.898,21.978) AW47(-28.723,21.978) AW49(-29.473,21.978) AW50(-30.298,21.978) AW51(-30.98,21.653) AW52(-31.656,21.978) AW53(-32.331,21.653) AW54(-33.007,21.978) AW56(-34.087,21.978) AW57(-34.762,21.653) AW58(-35.438,21.978) AW59(-36.002,21.653) AW60(-36.566,21.978) AY6(-3.375,22.628) AY7(-4.125,22.628) AY8(-4.874,22.628) AY10(-5.623,22.628) AY11(-6.373,22.628) AY12(-7.122,22.628) AY14(-7.871,22.628) AY15(-8.621,22.628) AY16(-9.184,22.303) AY17(-9.86,22.628) AY18(-10.536,22.303) AY19(-11.211,22.628) AY21(-12.291,22.628) AY22(-12.966,22.303) AY23(-13.642,22.628) AY24(-14.318,22.303) AY25(-14.993,22.628) AY26(-15.669,22.303) AY27(-16.345,22.628) AY29(-17.424,22.628) AY30(-18.1,22.303) AY31(-18.775,22.628) AY33(-19.451,22.303) AY34(-20.024,22.628) AY35(-20.849,22.628) AY36(-21.599,22.628) AY37(-22.424,22.628) AY39(-23.173,22.628) AY40(-23.999,22.628) AY41(-24.748,22.628) AY42(-25.574,22.628) AY43(-26.323,22.628) AY44(-27.149,22.628) AY46(-27.898,22.628) AY47(-28.723,22.628) AY49(-29.473,22.628) AY50(-30.298,22.628) AY51(-30.98,22.303) AY52(-31.656,22.628) AY53(-32.331,22.303) AY54(-33.007,22.628) AY56(-34.087,22.628) AY57(-34.762,22.303) AY58(-35.438,22.628) B4(-1.922,0.65) B5(-3.138,0.643) B6(-4.119,0.643) B8(-4.891,0.643) B9(-5.716,0.643) B11(-6.697,0.643) B12(-7.469,0.643) B14(-8.294,0.643) B15(-9.275,0.643) B17(-10.047,0.643) B18(-10.872,0.643) B20(-11.853,0.643) B21(-12.272,1.196) B22(-12.625,0.643) B23(-13.451,0.643) B24(-14.023,0.975) B25(-14.714,0.65) B26(-15.277,0.975) B27(-15.84,0.65) B28(-16.531,0.975) B29(-17.221,0.65) B30(-17.785,0.975) B31(-18.348,0.65) B32(-19.038,0.975) B33(-19.729,0.65) B34(-20.292,0.975) B35(-20.855,0.65) B36(-21.546,0.975) B37(-22.236,0.65) B38(-22.8,0.975) B39(-23.363,0.65) B40(-24.053,0.975) B41(-24.744,0.65) B42(-25.307,0.975) B43(-25.87,0.65) B44(-26.561,0.975) B45(-27.251,0.65) B46(-27.815,0.975) B47(-28.378,0.65) B48(-29.068,0.975) B49(-29.759,0.65) B50(-30.322,0.975) B51(-30.885,0.65) B52(-31.576,0.975) B53(-32.266,0.65) B54(-32.83,0.975) B55(-33.393,0.65) B56(-34.083,0.975) B57(-34.774,0.65) B58(-35.337,0.975) B59(-35.9,0.65) B60(-36.665,0.66) C3(-1.302,1.302) C4(-2.118,1.272) C5(-2.772,1.196) C6(-3.776,1.196) C8(-4.538,1.196) C9(-5.351,1.196) C11(-6.354,1.196) C12(-7.116,1.196) C14(-7.929,1.196) C15(-8.932,1.196) C17(-9.694,1.196) C18(-10.507,1.196) C20(-11.51,1.196) C21(-11.891,1.786) C22(-12.678,1.786) C23(-13.085,1.196) C24(-14.051,2.032) C25(-14.714,1.3) C26(-15.277,1.626) C27(-15.84,1.3) C28(-16.558,2.032) C29(-17.221,1.3) C30(-17.785,1.626) C31(-18.348,1.3) C32(-19.066,2.032) C33(-19.729,1.3) C34(-20.292,1.626) C35(-20.855,1.3) C36(-21.573,2.032) C37(-22.236,1.3) C38(-22.8,1.626) C39(-23.363,1.3) C40(-24.081,2.032) C41(-24.744,1.3) C42(-25.307,1.626) C43(-25.87,1.3) C44(-26.588,2.032) C45(-27.251,1.3) C46(-27.815,1.626) C47(-28.378,1.3) C48(-29.07,2.032) C49(-29.759,1.3) C50(-30.322,1.626) C51(-30.885,1.3) C52(-31.578,1.991) C53(-32.266,1.3) C54(-32.83,1.626) C55(-33.393,1.3) C56(-34.085,1.991) C57(-34.774,1.3) C58(-35.337,1.626) C59(-35.9,1.3) C61(-37.003,1.237) D2(-0.65,2.075) D3(-1.3,2.037) D5(-2.678,1.842) D6(-3.369,1.786) D8(-4.157,1.786) D9(-4.944,1.786) D11(-5.852,1.786) D12(-6.735,1.786) D14(-7.522,1.786) D15(-8.43,1.786) D17(-9.313,1.786) D18(-10.1,1.786) D20(-11.008,1.786) D21(-12.235,2.423) D23(-13.377,1.786) D25(-14.714,1.951) D26(-15.277,2.276) D27(-15.84,1.951) D29(-17.221,1.951) D30(-17.785,2.276) D31(-18.348,1.951) D33(-19.729,1.951) D34(-20.292,2.276) D35(-20.855,1.951) D37(-22.236,1.951) D38(-22.8,2.276) D39(-23.363,1.951) D41(-24.744,1.951) D42(-25.307,2.276) D43(-25.87,1.951) D45(-27.251,1.951) D46(-27.815,2.276) D47(-28.378,1.951) D49(-29.759,1.951) D50(-30.322,2.276) D51(-30.885,1.951) D53(-32.266,1.951) D54(-32.83,2.276) D55(-33.393,1.951) D57(-34.774,1.951) D58(-35.337,2.276) D59(-35.9,1.951) D60(-36.678,1.801) D61(-37.328,1.801) D62(-37.978,2.035) E2(-0.65,2.725) E3(-1.3,2.687) E4(-1.951,2.687) E5(-2.602,2.619) E6(-3.554,2.619) E8(-4.507,2.619) E10(-5.459,2.619) E11(-6.412,2.619) E13(-7.364,2.619) E15(-8.317,2.619) E17(-9.269,2.619) E18(-10.222,2.619) E20(-11.174,2.619) E59(-36.027,2.647) E60(-36.678,2.647) E61(-37.328,2.647) E62(-37.978,2.685) F2(-0.65,3.474) F3(-1.3,3.512) F4(-1.951,3.512) F5(-2.602,3.269) F6(-3.554,3.269) F8(-4.507,3.269) F10(-5.459,3.269) F11(-6.412,3.269) F13(-7.364,3.269) F15(-8.317,3.269) F17(-9.269,3.269) F18(-10.222,3.269) F20(-11.174,3.269) F59(-36.027,3.472) F60(-36.678,3.472) F61(-37.328,3.472) F62(-37.978,3.434) F63(-38.628,3.434) G1(0,4.224) G2(-0.65,4.224) G3(-1.3,4.185) G4(-1.951,4.185) G5(-2.602,3.919) G6(-3.554,3.919) G8(-4.507,3.919) G10(-5.459,3.919) G11(-6.412,3.919) G13(-7.364,3.919) G15(-8.317,3.919) G17(-9.269,3.919) G18(-10.222,3.919) G20(-11.174,3.919) H5(-2.602,4.569) H6(-3.554,4.569) H8(-4.507,4.569) H10(-5.459,4.569) H11(-6.412,4.569) H13(-7.364,4.569) H15(-8.317,4.569) H17(-9.269,4.569) H18(-10.222,4.569) H20(-11.174,4.569) H59(-36.027,4.145) H60(-36.678,4.145) H61(-37.328,4.145) H62(-37.978,4.183) H63(-38.628,4.183) J1(0,4.973) J2(-0.65,4.973) J3(-1.3,5.011) J4(-1.951,5.011) J5(-2.627,5.22) J6(-3.567,5.22) J8(-4.507,5.22) J10(-5.459,5.22) J11(-6.412,5.22) J13(-7.364,5.22) J15(-8.317,5.22) J17(-9.269,5.22) J18(-10.222,5.22) J20(-11.174,5.22) J21(-12.095,4.986) J59(-36.027,4.971) J60(-36.678,4.971) J61(-37.328,4.971) J62(-37.978,4.933) J63(-38.628,4.933) K1(0,5.722) K2(-0.65,5.722) K3(-1.3,5.684) K4(-1.951,5.684) K59(-36.027,5.644) K60(-36.678,5.644) K61(-37.328,5.644) K62(-37.978,5.682) K63(-38.628,5.682) L1(0,6.471) L2(-0.65,6.471) L3(-1.3,6.51) L4(-1.951,6.51) L5(-2.637,6.338) L6(-3.287,6.338) L7(-3.937,6.338) L8(-4.587,6.338) L59(-36.027,6.469) L60(-36.678,6.469) L61(-37.328,6.469) L62(-37.978,6.431) L63(-38.628,6.431) N1(0,7.221) N2(-0.65,7.221) N3(-1.3,7.183) N4(-1.951,7.183) N5(-2.637,7.29) N6(-3.287,7.29) N7(-3.937,7.29) N8(-4.587,7.29) N59(-36.027,7.142) N60(-36.678,7.142) N61(-37.328,7.142) N62(-37.978,7.181) N63(-38.628,7.181) P1(0,7.97) P2(-0.65,7.97) P3(-1.3,8.008) P4(-1.951,8.008) P59(-36.027,7.968) P60(-36.678,7.968) P61(-37.328,7.968) P62(-37.978,7.93) P63(-38.628,7.93) R5(-2.637,8.243) R6(-3.287,8.243) R7(-3.937,8.243) R8(-4.587,8.243) T1(0,8.719) T2(-0.65,8.719) T3(-1.3,8.681) T4(-1.951,8.681) T59(-36.027,8.641) T60(-36.678,8.641) T61(-37.328,8.641) T62(-37.978,8.679) T63(-38.628,8.679) U1(0,9.469) U2(-0.65,9.469) U3(-1.3,9.507) U4(-1.951,9.507) U5(-2.637,9.195) U6(-3.287,9.195) U7(-3.937,9.195) U8(-4.587,9.195) U59(-36.027,9.467) U60(-36.678,9.467) U61(-37.328,9.467) U62(-37.978,9.428) U63(-38.628,9.428) V1(0,10.218) V2(-0.65,10.218) V3(-1.3,10.18) V4(-1.951,10.18) V5(-2.637,10.148) V6(-3.287,10.148) V7(-3.937,10.148) V8(-4.587,10.148) V59(-36.027,10.14) V60(-36.678,10.14) V61(-37.328,10.14) V62(-37.978,10.178) V63(-38.628,10.178) Y1(0,10.967) Y2(-0.65,10.967) Y3(-1.3,11.005) Y4(-1.951,11.005) Y5(-2.637,11.1) Y6(-3.287,11.1) Y7(-3.937,11.1) Y8(-4.587,11.1) Y59(-36.027,10.965) Y60(-36.678,10.965) Y61(-37.328,10.965) Y62(-37.978,10.927) Y63(-38.628,10.927)
  round 0.33 smd: AK22(-12.655,16.266) AK23(-13.529,16.266) AK25(-14.504,16.266) AK26(-15.456,16.266) AK28(-16.409,16.266) AK29(-17.311,16.266) AK32(-18.824,16.266) AK33(-19.726,16.266) AK35(-20.729,16.266) AK36(-21.58,16.266) AK38(-22.609,16.266) AK40(-24.106,16.266) AK42(-24.944,16.266) AK43(-25.897,16.266) AK45(-26.874,16.266) AK46(-27.776,16.266) AK48(-28.83,16.266) AK49(-29.732,16.266) AK51(-30.735,16.266) AK52(-31.583,16.266) AK54(-32.61,16.266) AK55(-33.562,16.266) AK57(-34.509,16.266) AK58(-35.408,16.266)
